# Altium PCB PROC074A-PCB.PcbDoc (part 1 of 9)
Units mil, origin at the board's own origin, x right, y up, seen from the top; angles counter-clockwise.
Board outline 2755.91 x 5300 mil, 10 copper layers (Top Layer, L2-GND, L3-SIG1, L4-GND, L5-PWR/SIG, L6-SIG2, L7-PWR2, L8-SIG3, L9-GND, Bottom Layer), stack 67.57 mil thick; 585 components, 490 nets, 2137 pads, 1150 vias.
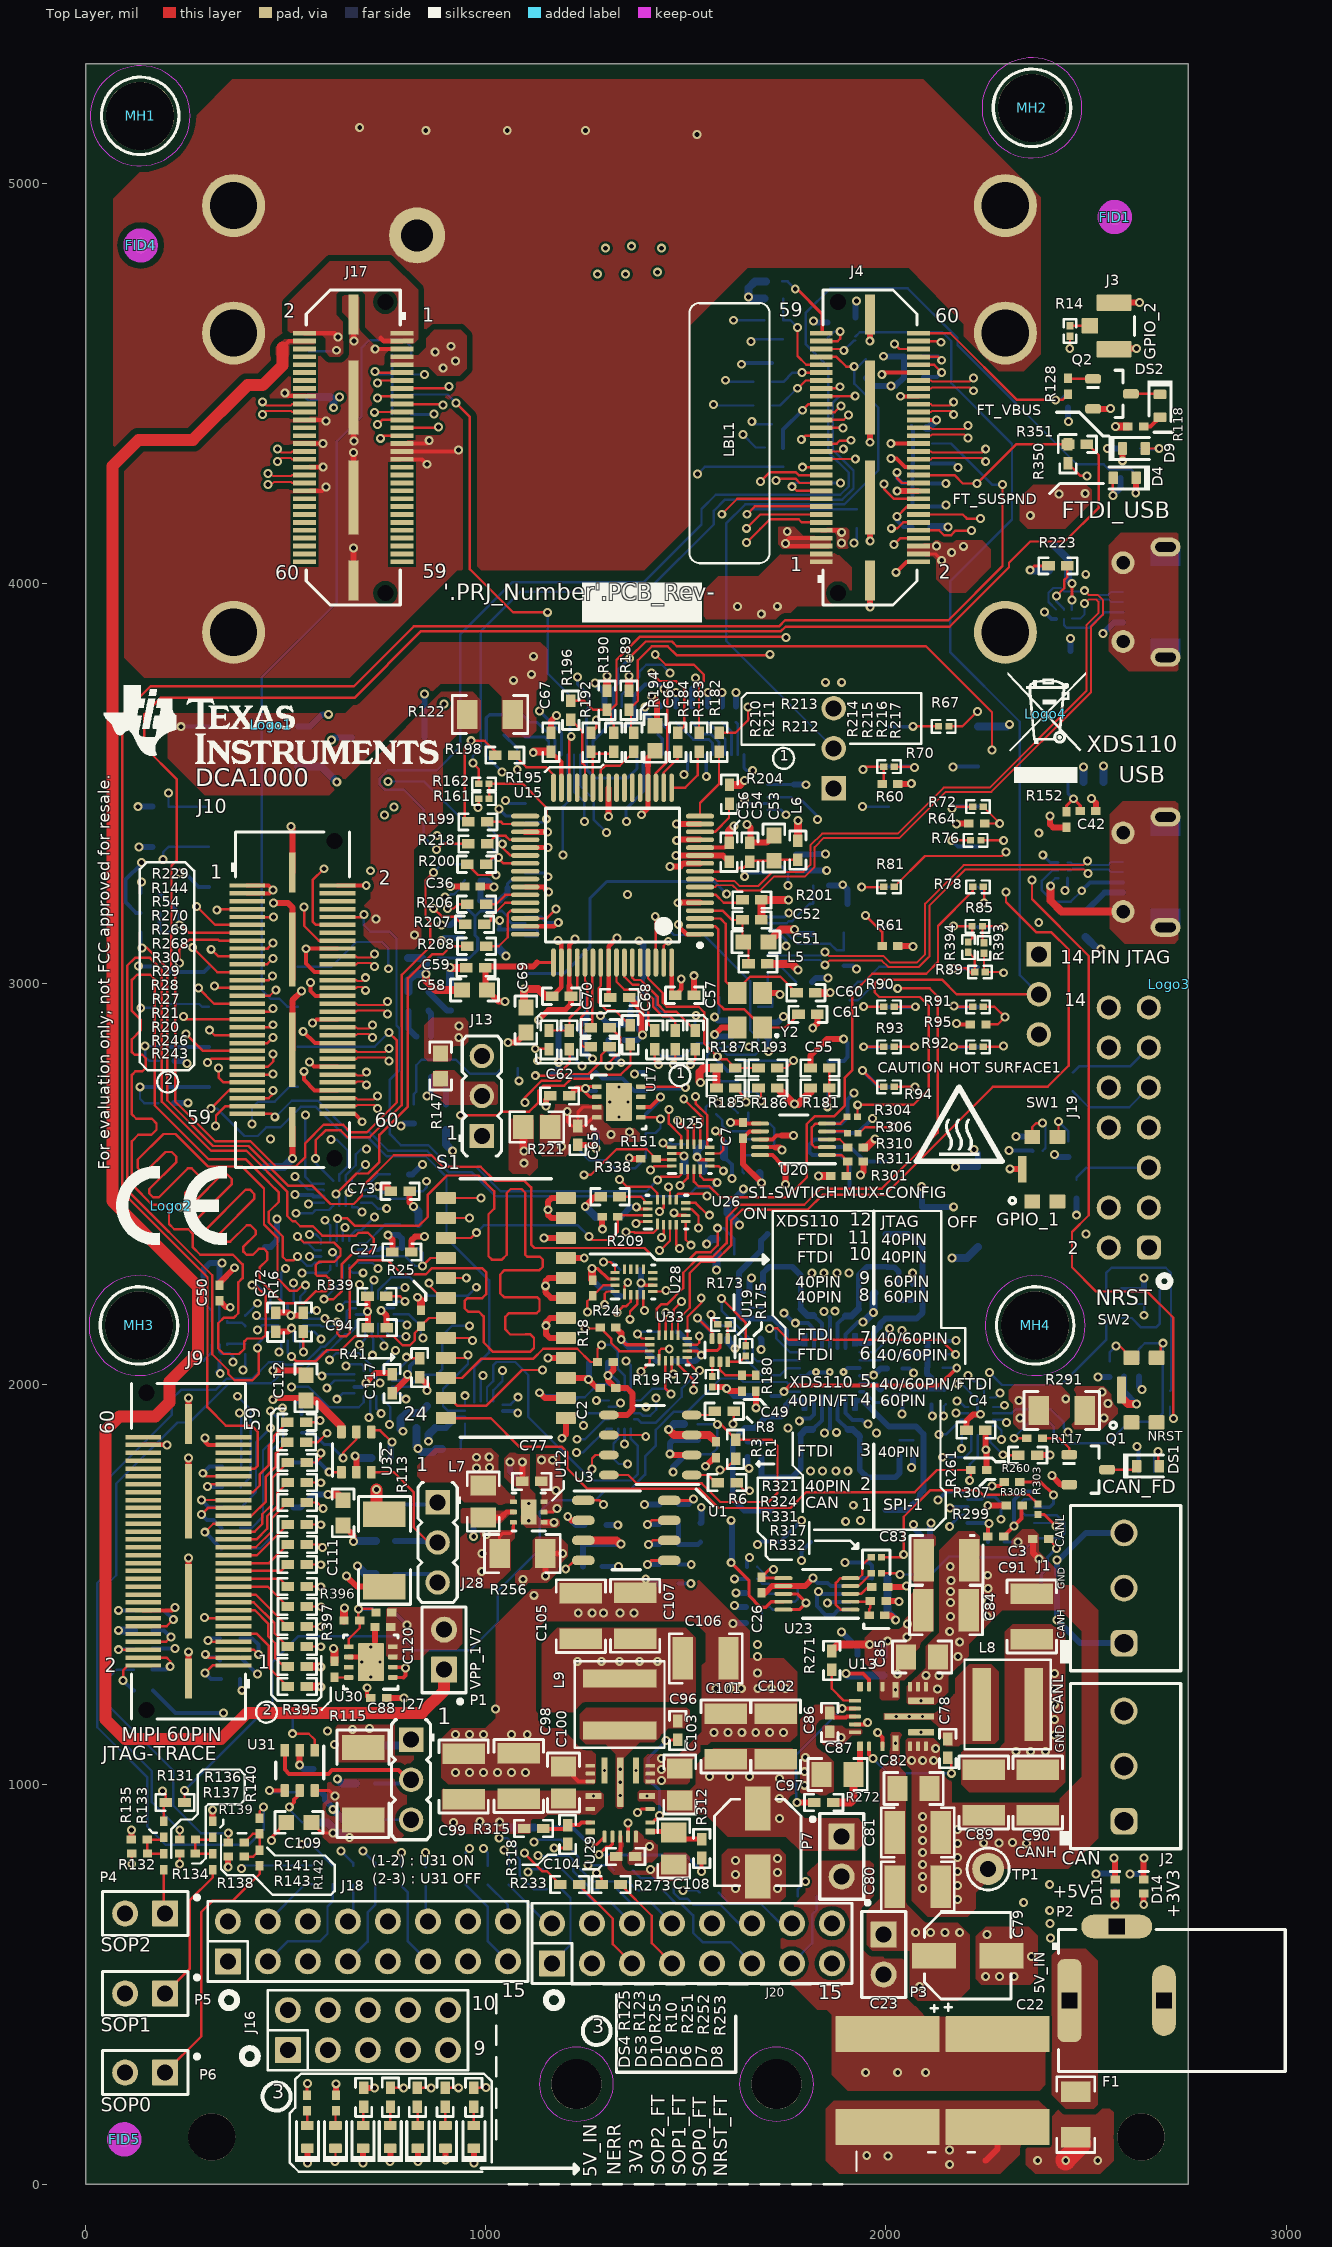
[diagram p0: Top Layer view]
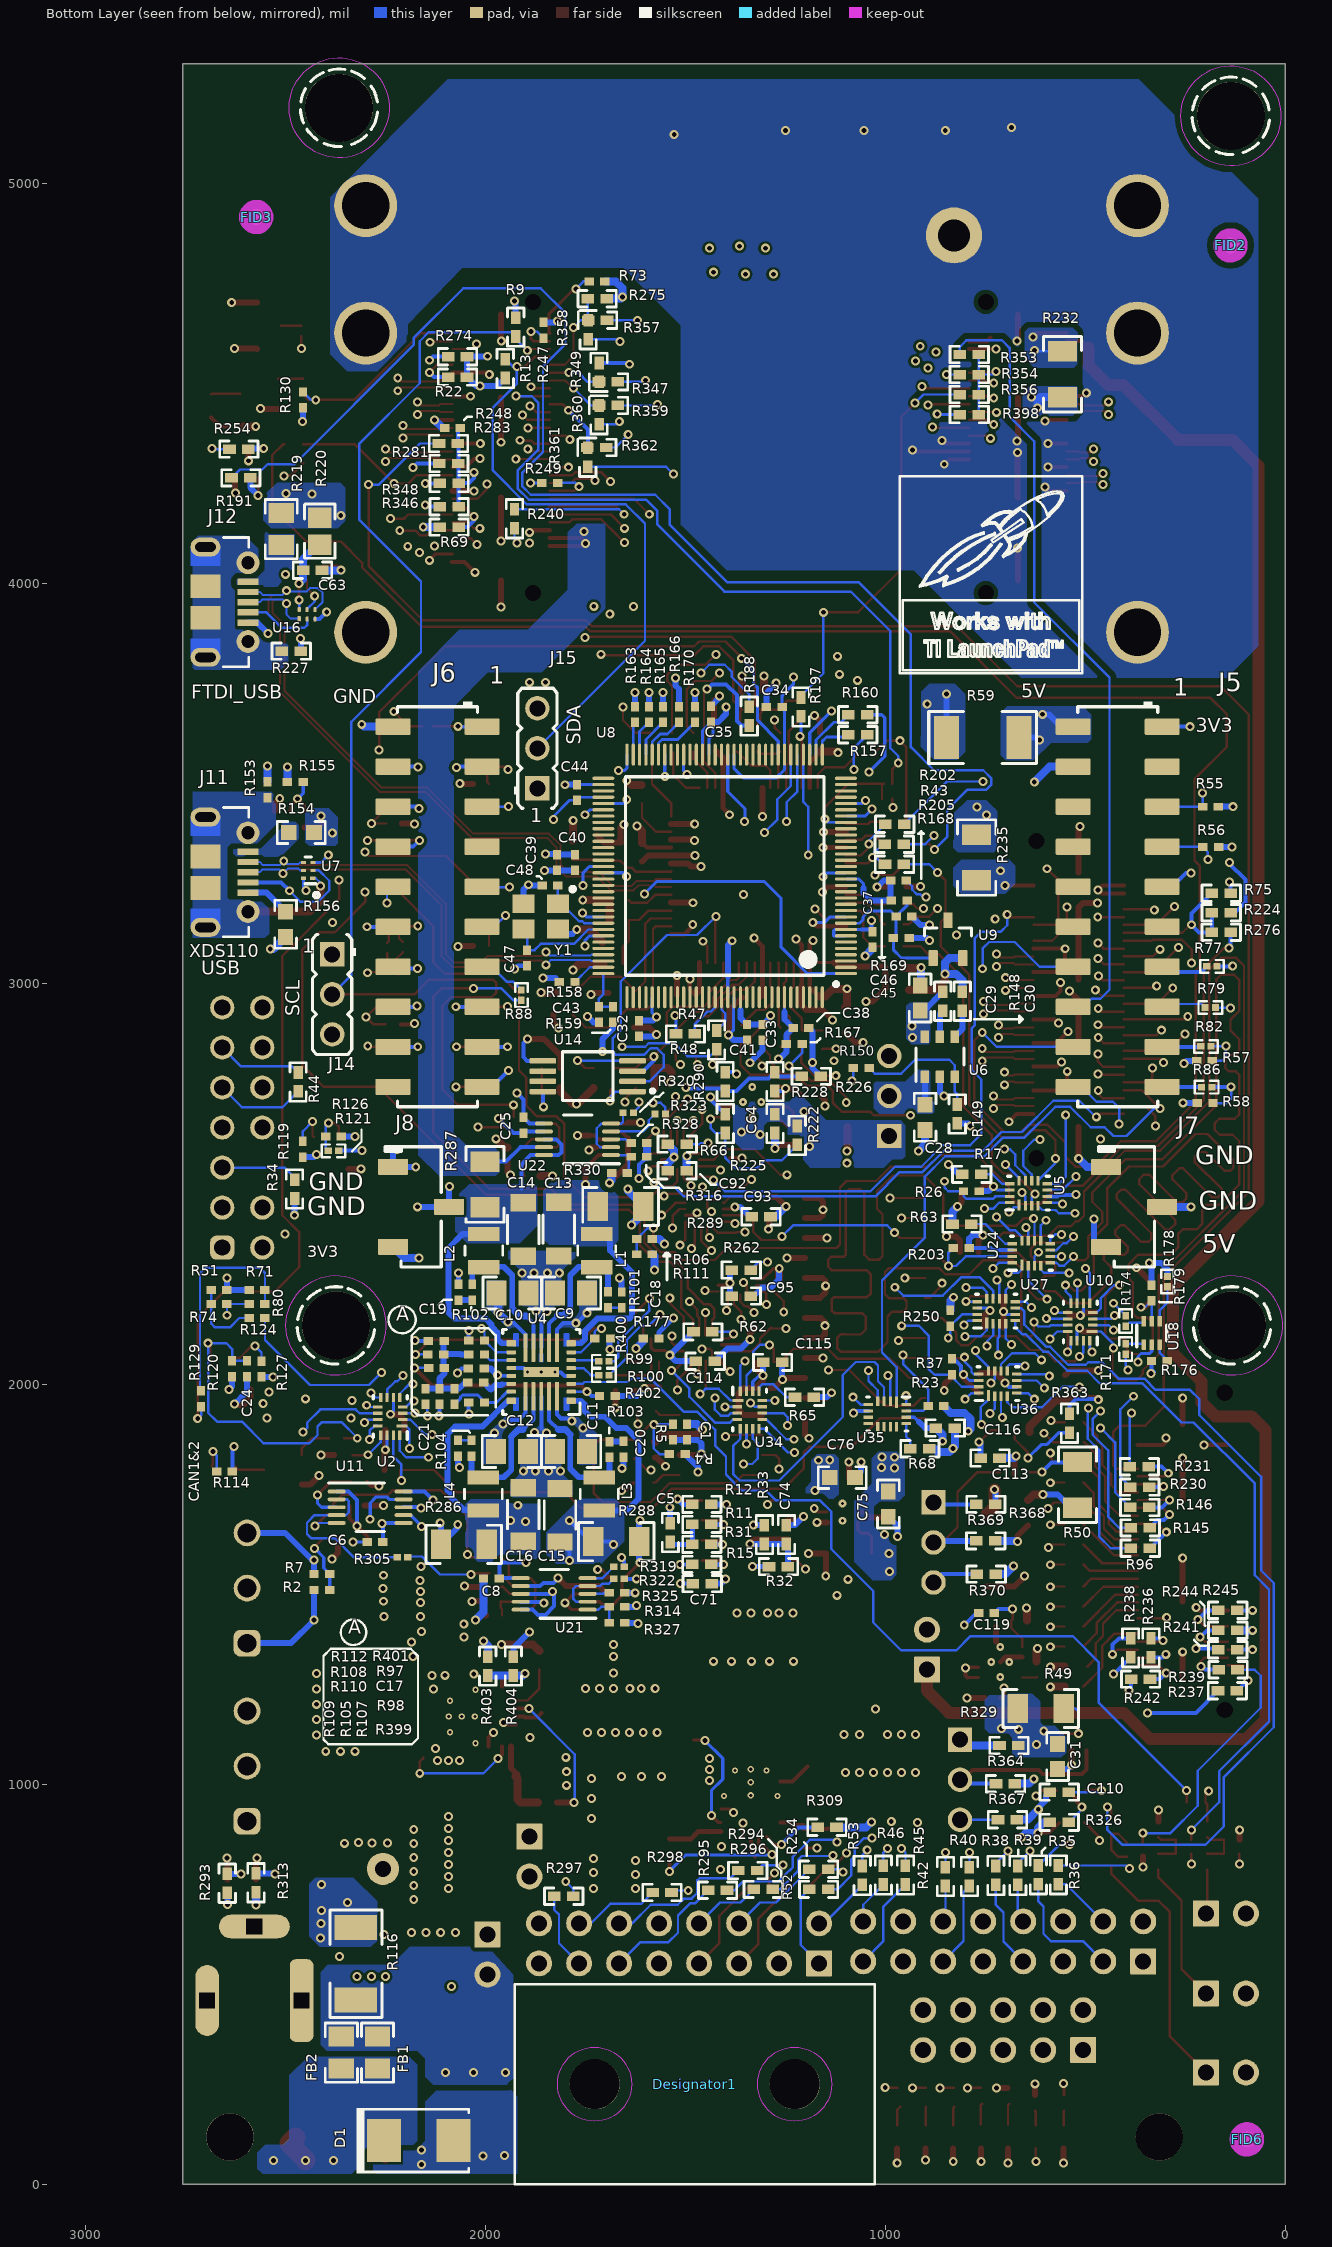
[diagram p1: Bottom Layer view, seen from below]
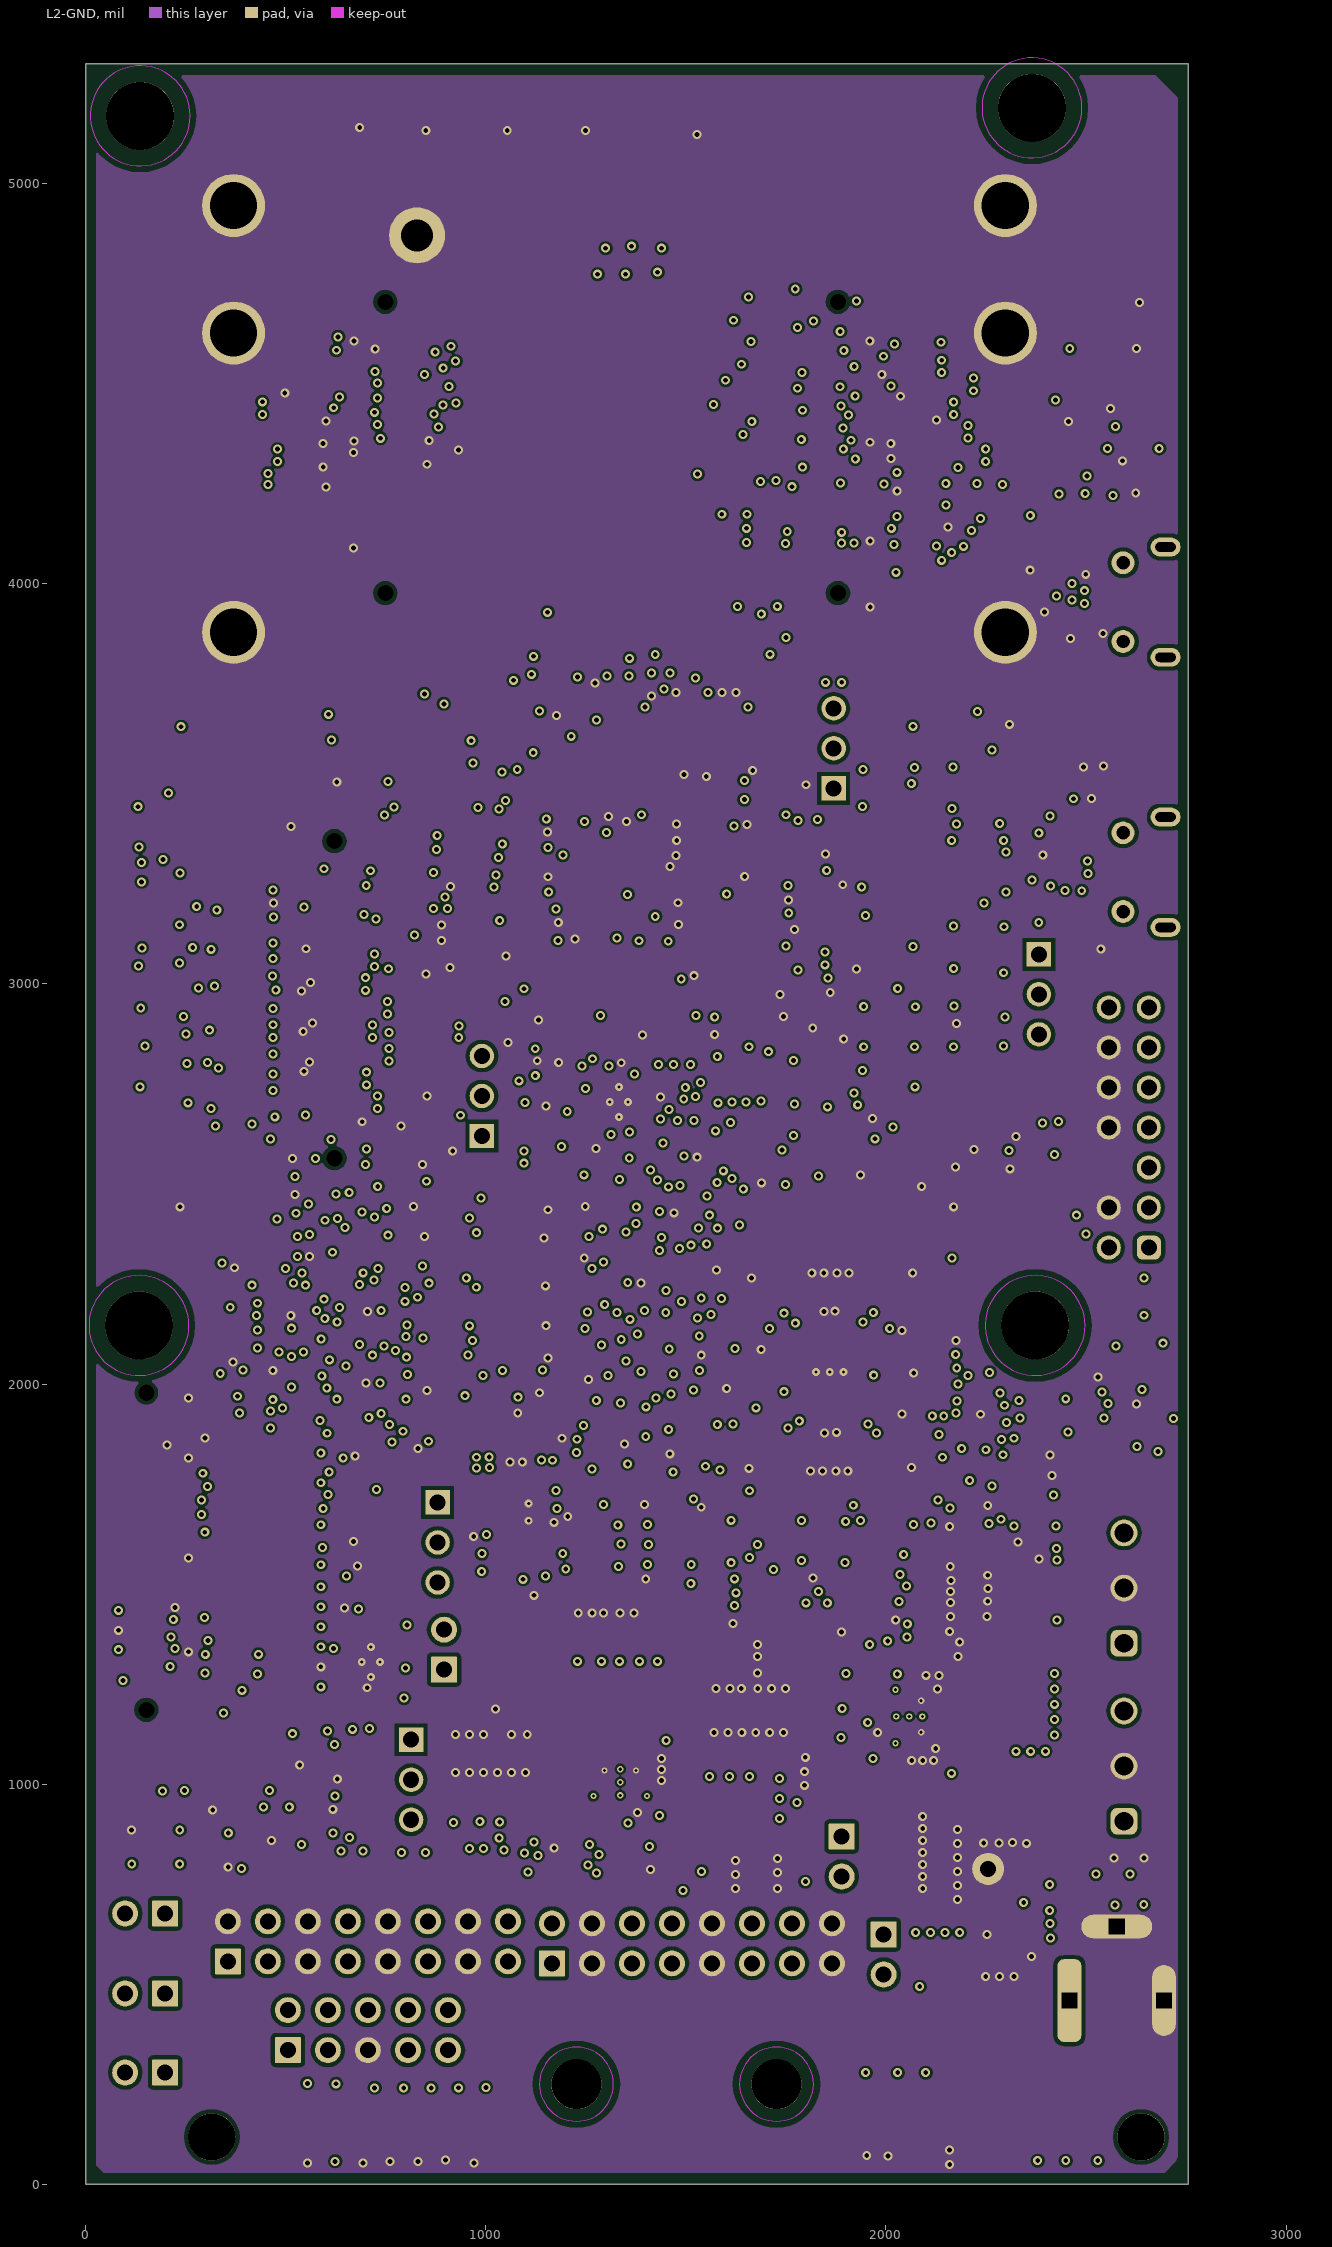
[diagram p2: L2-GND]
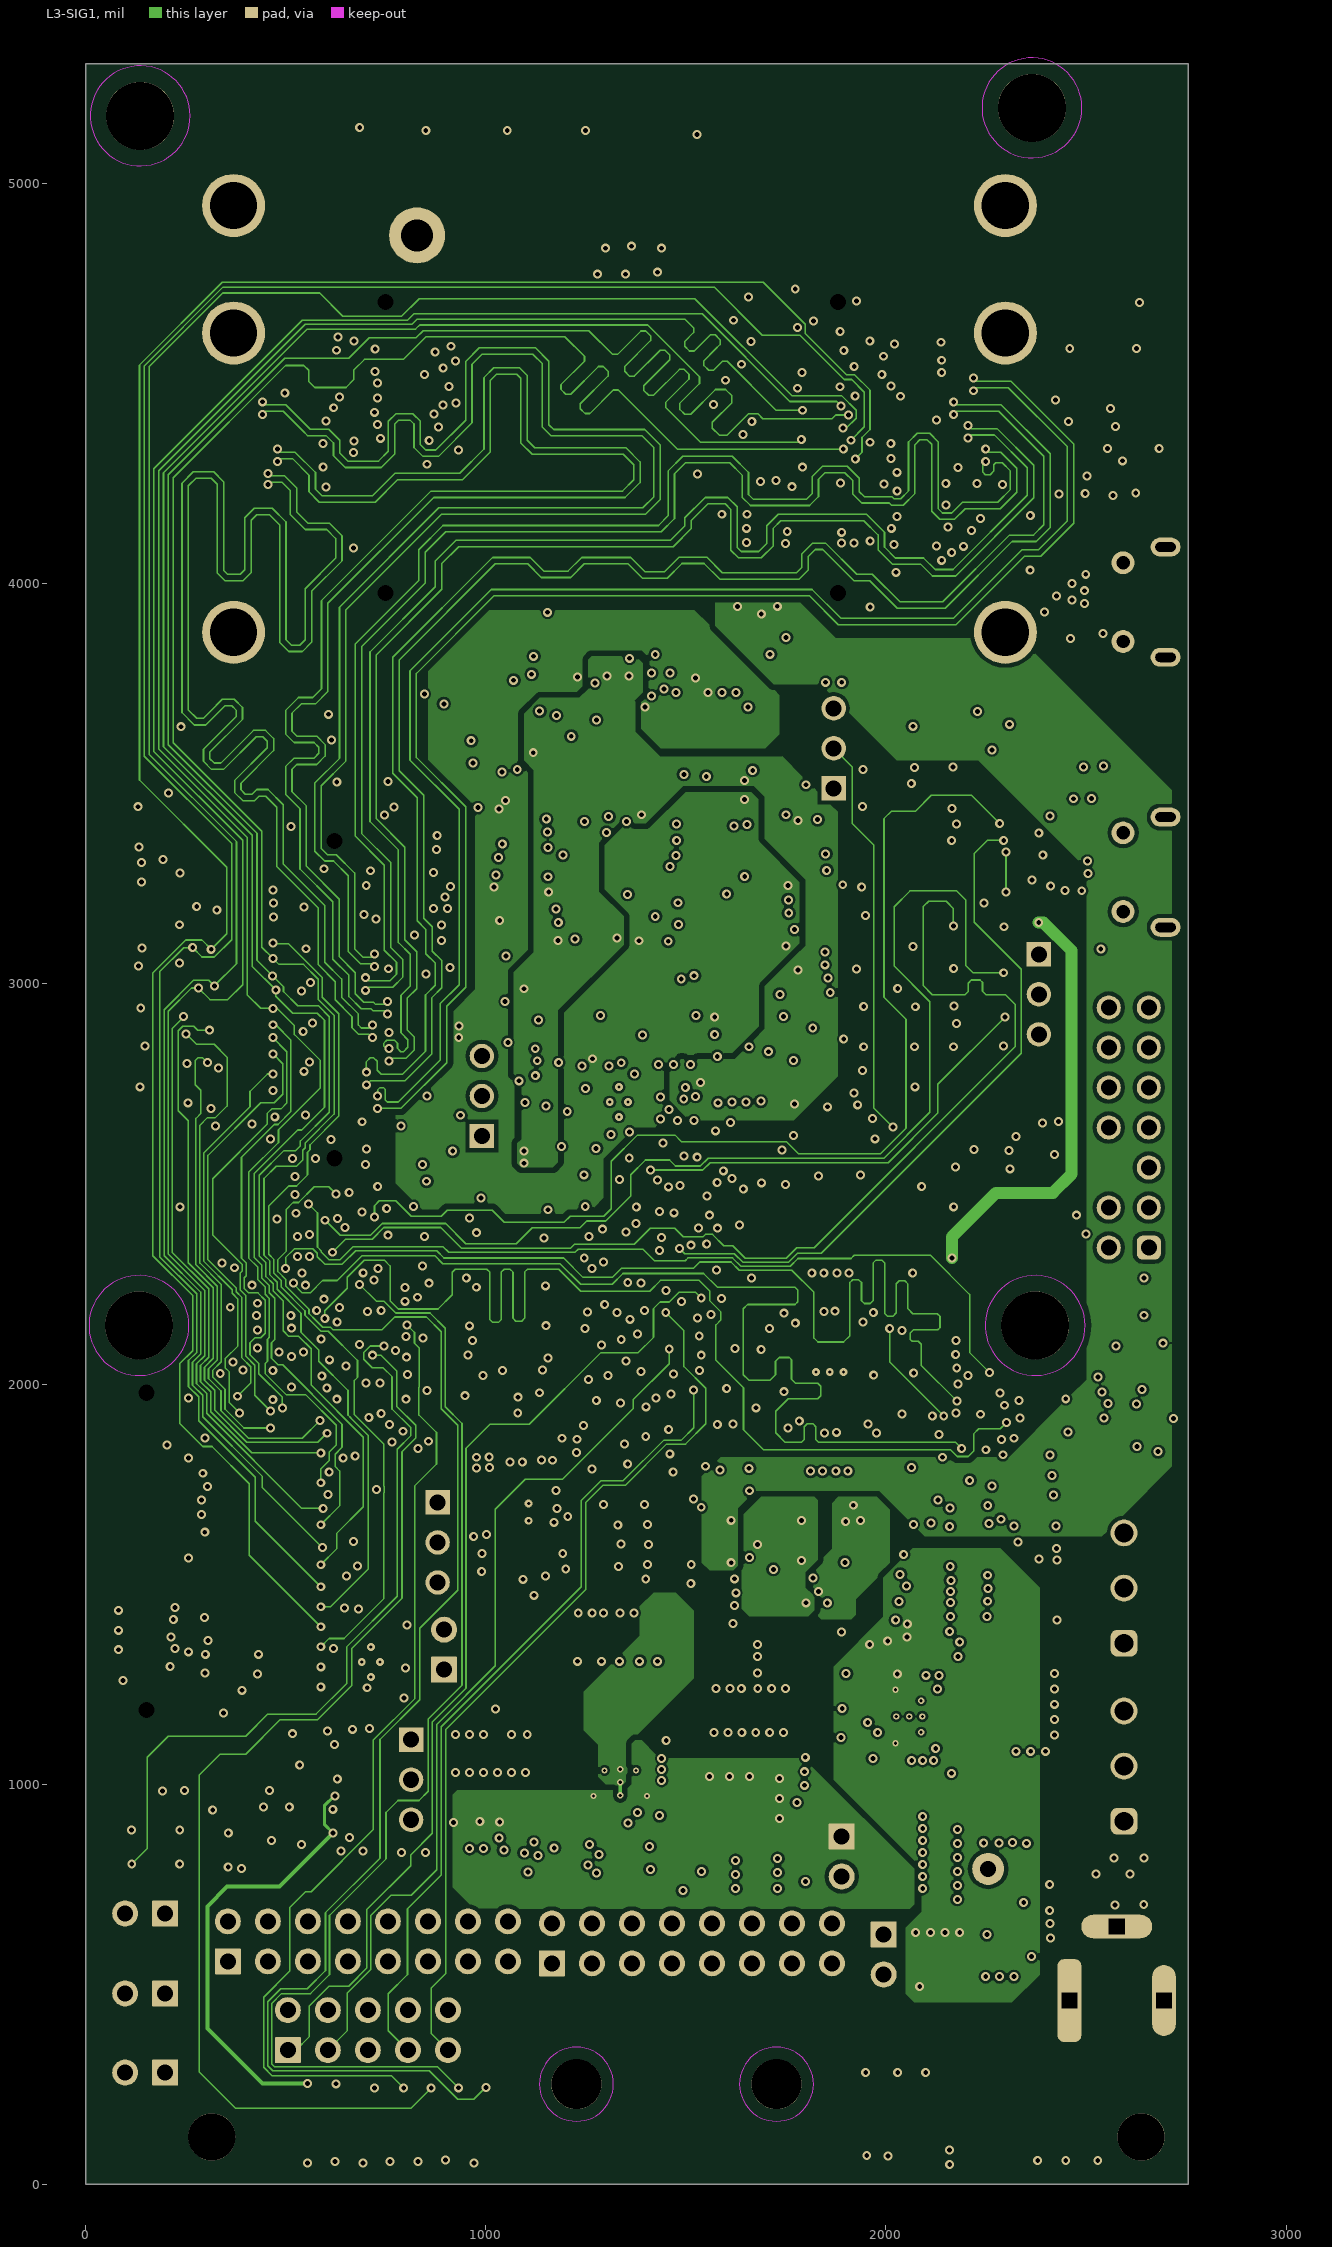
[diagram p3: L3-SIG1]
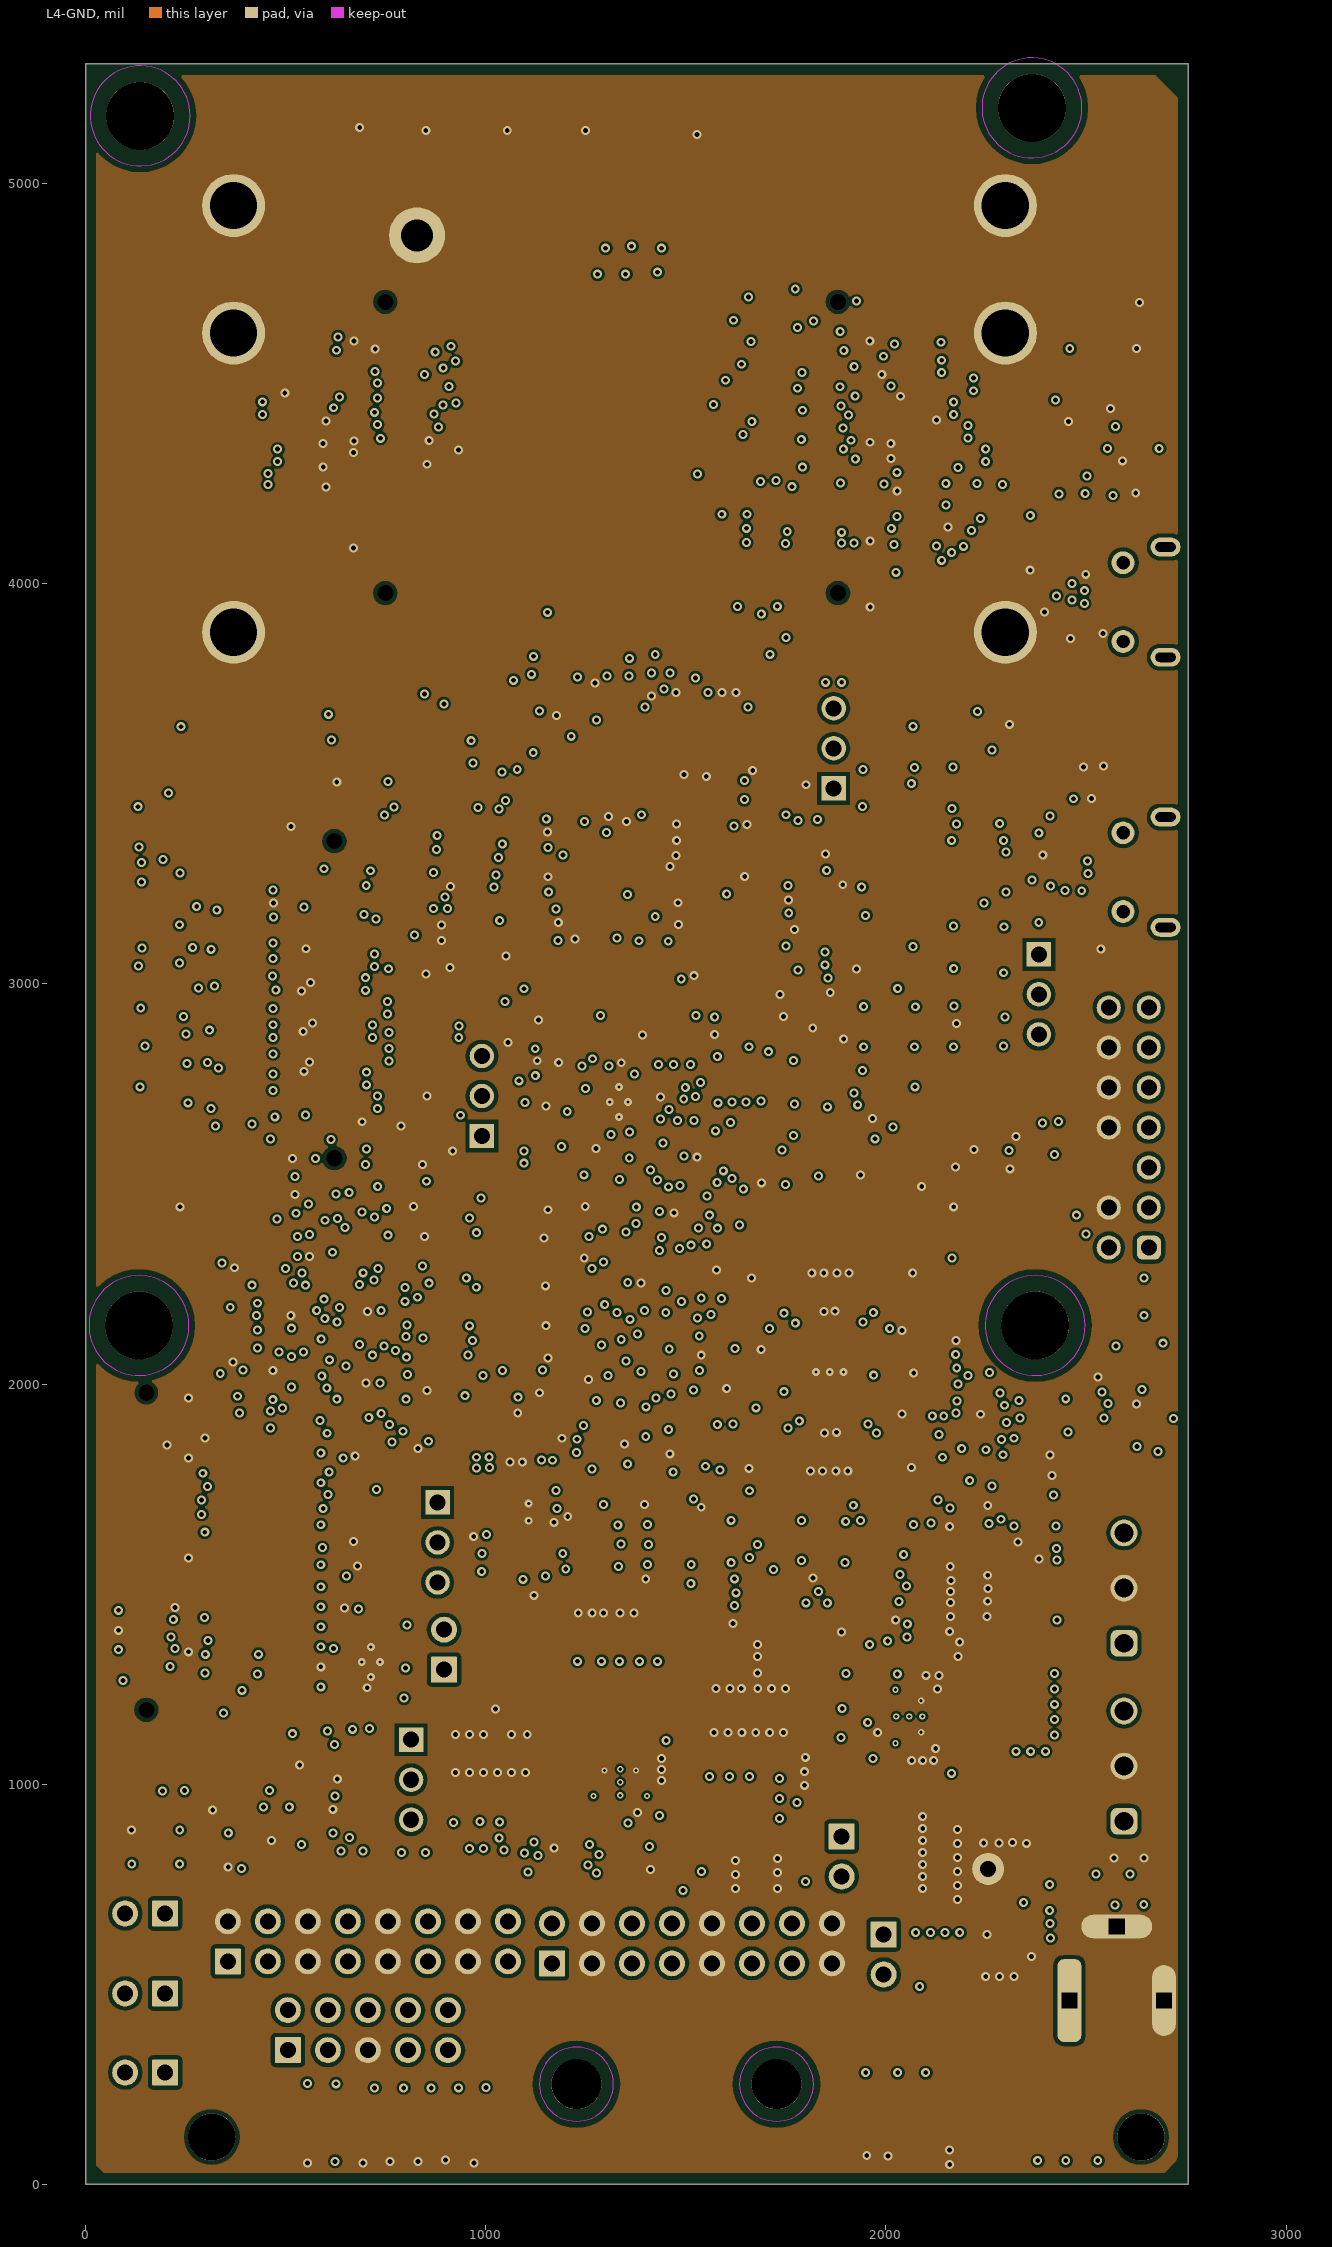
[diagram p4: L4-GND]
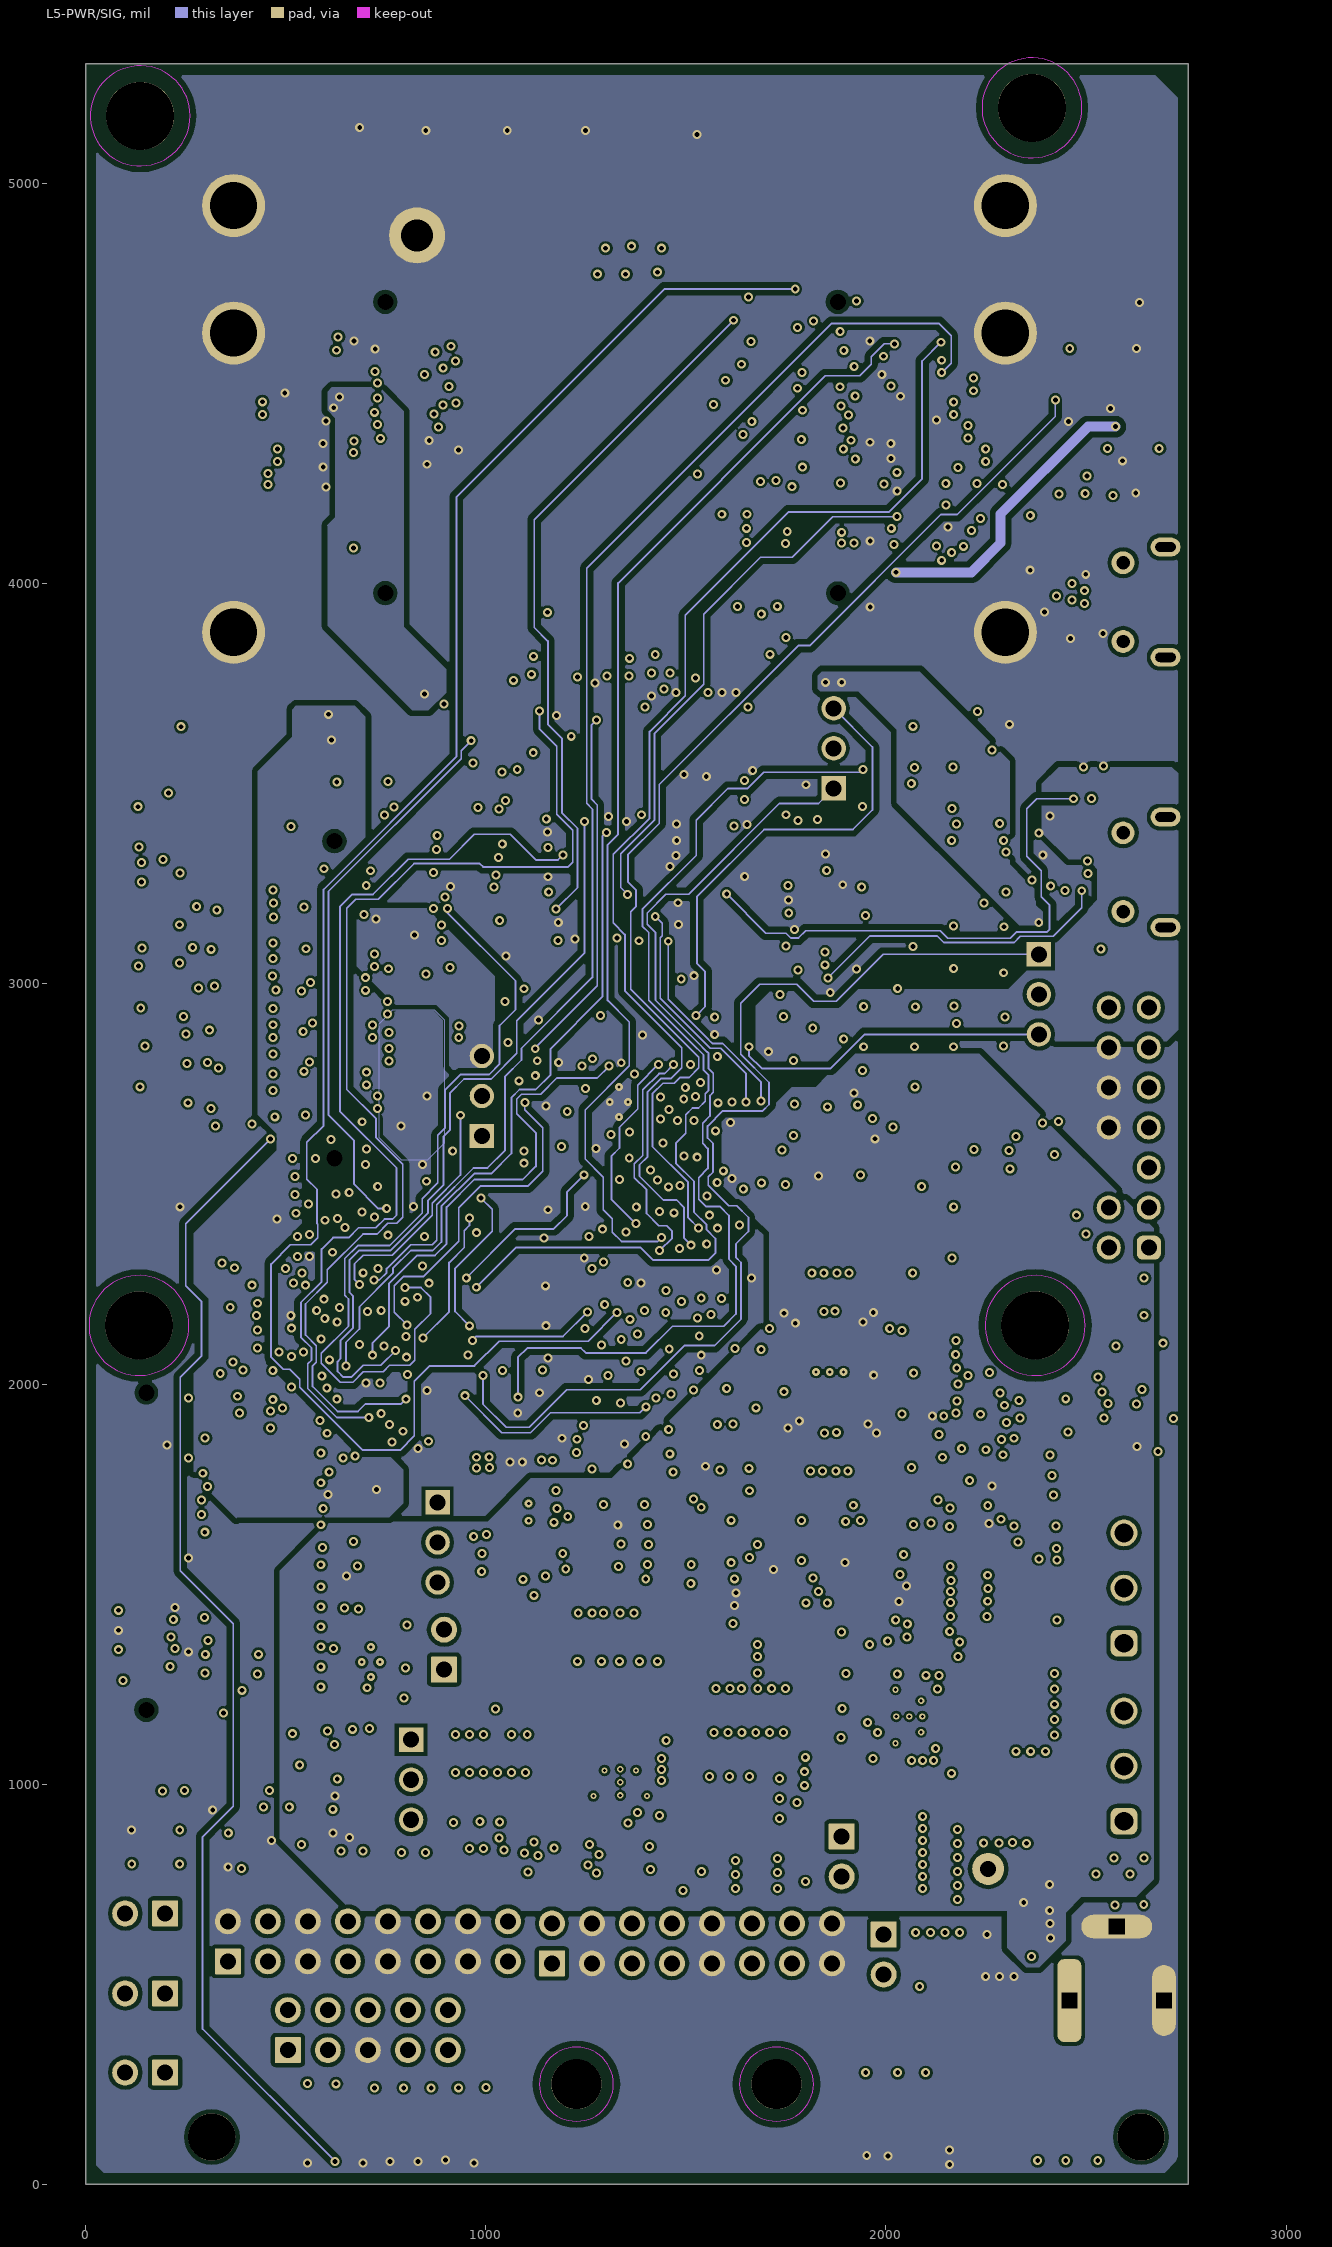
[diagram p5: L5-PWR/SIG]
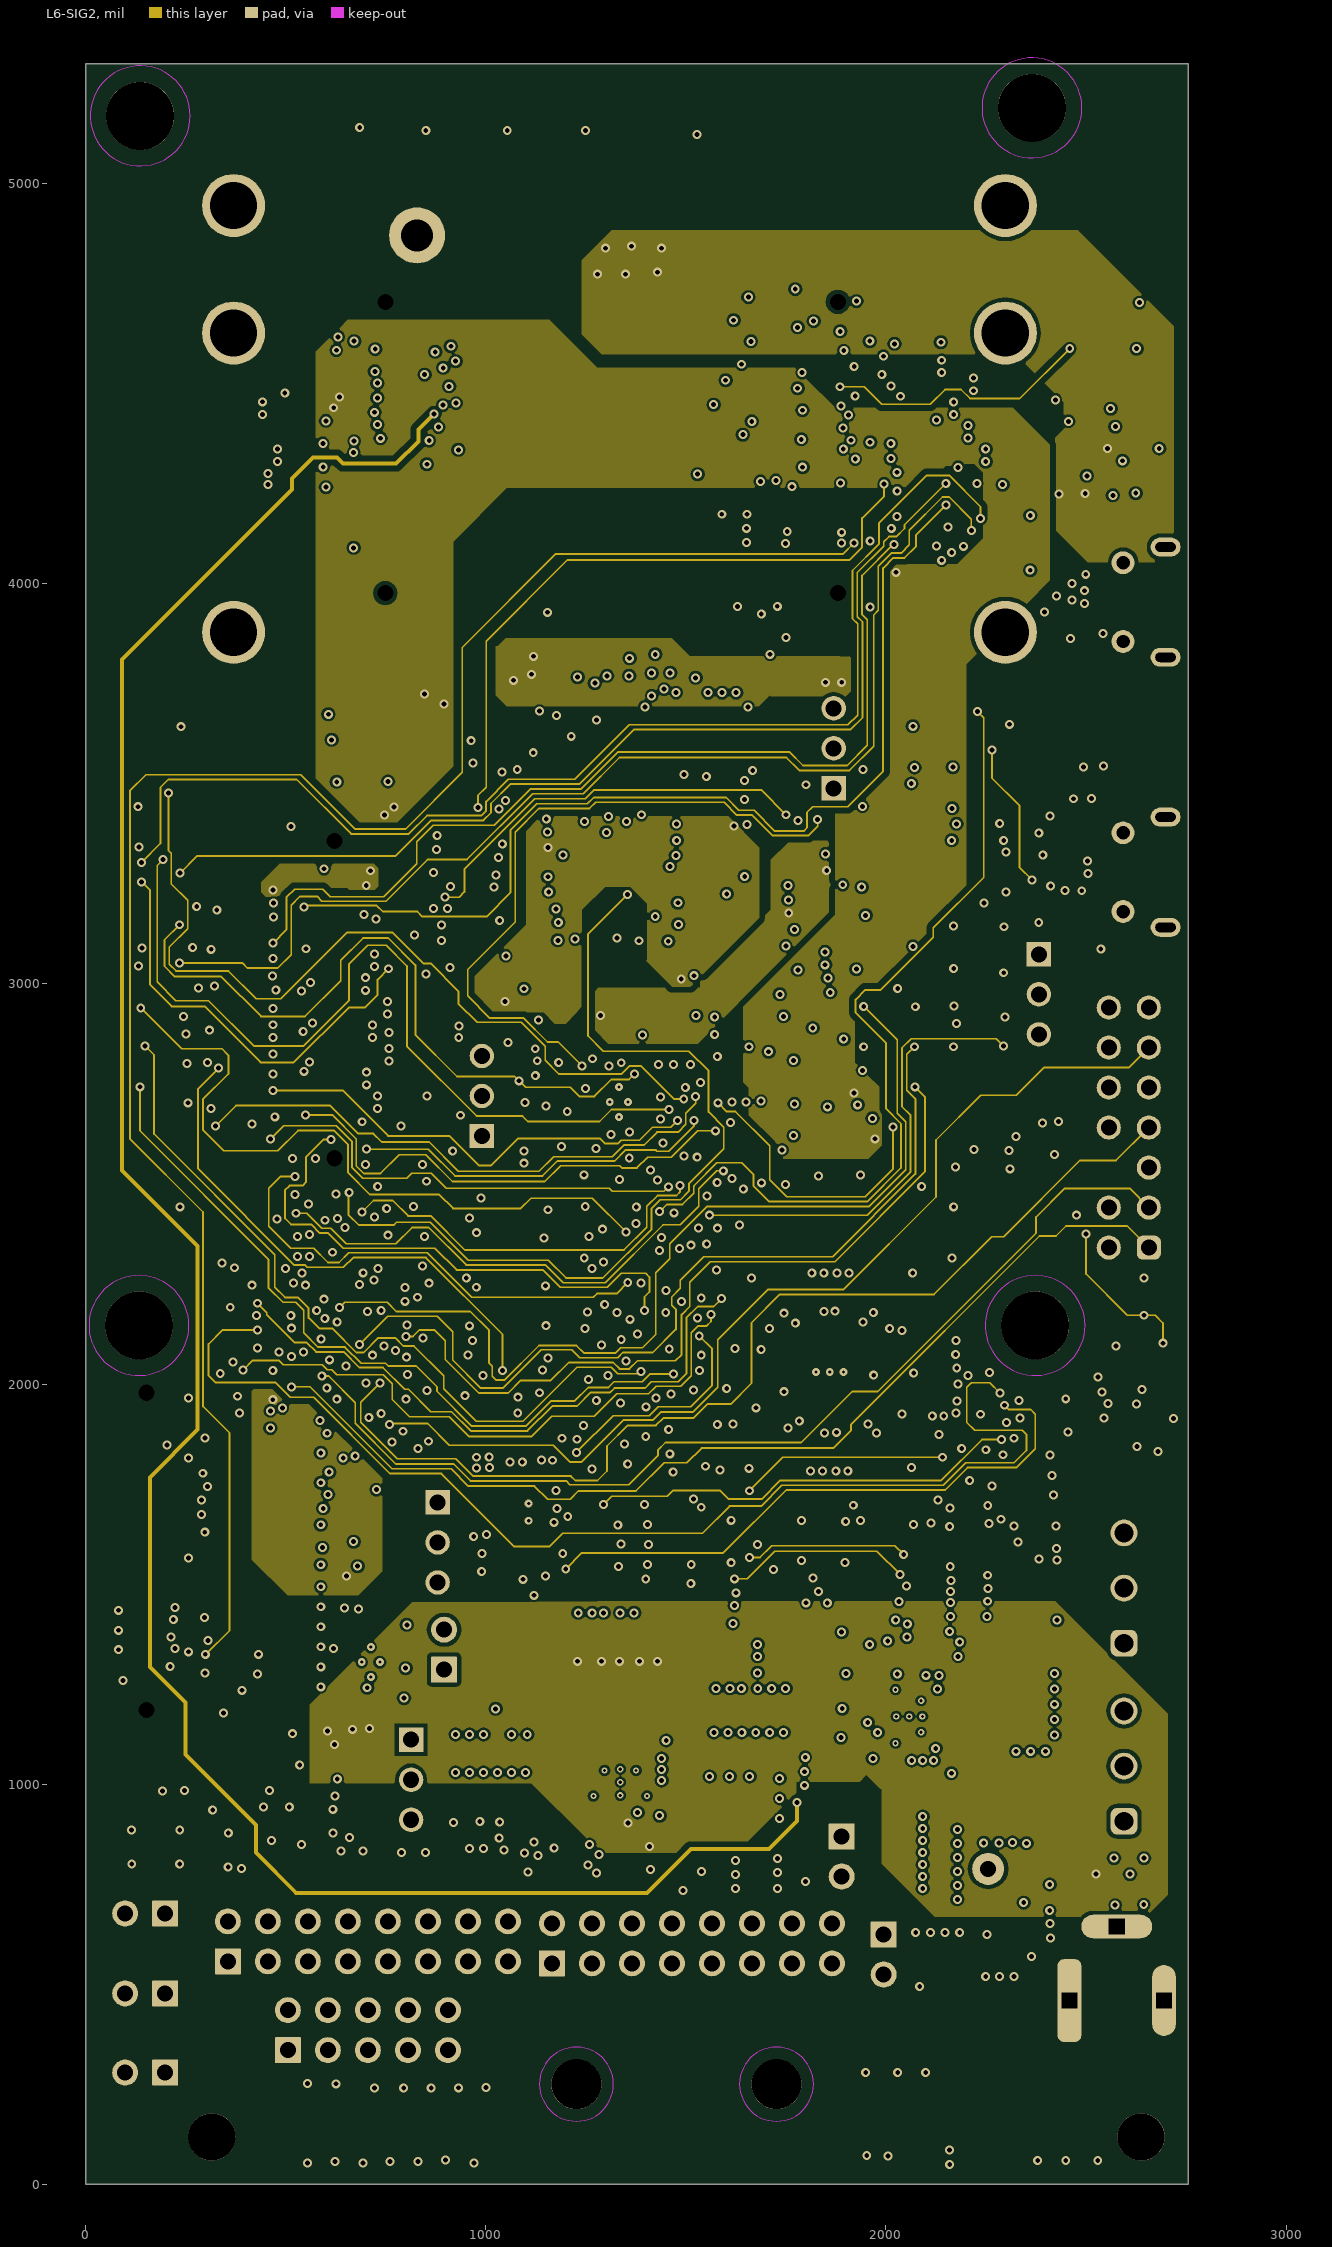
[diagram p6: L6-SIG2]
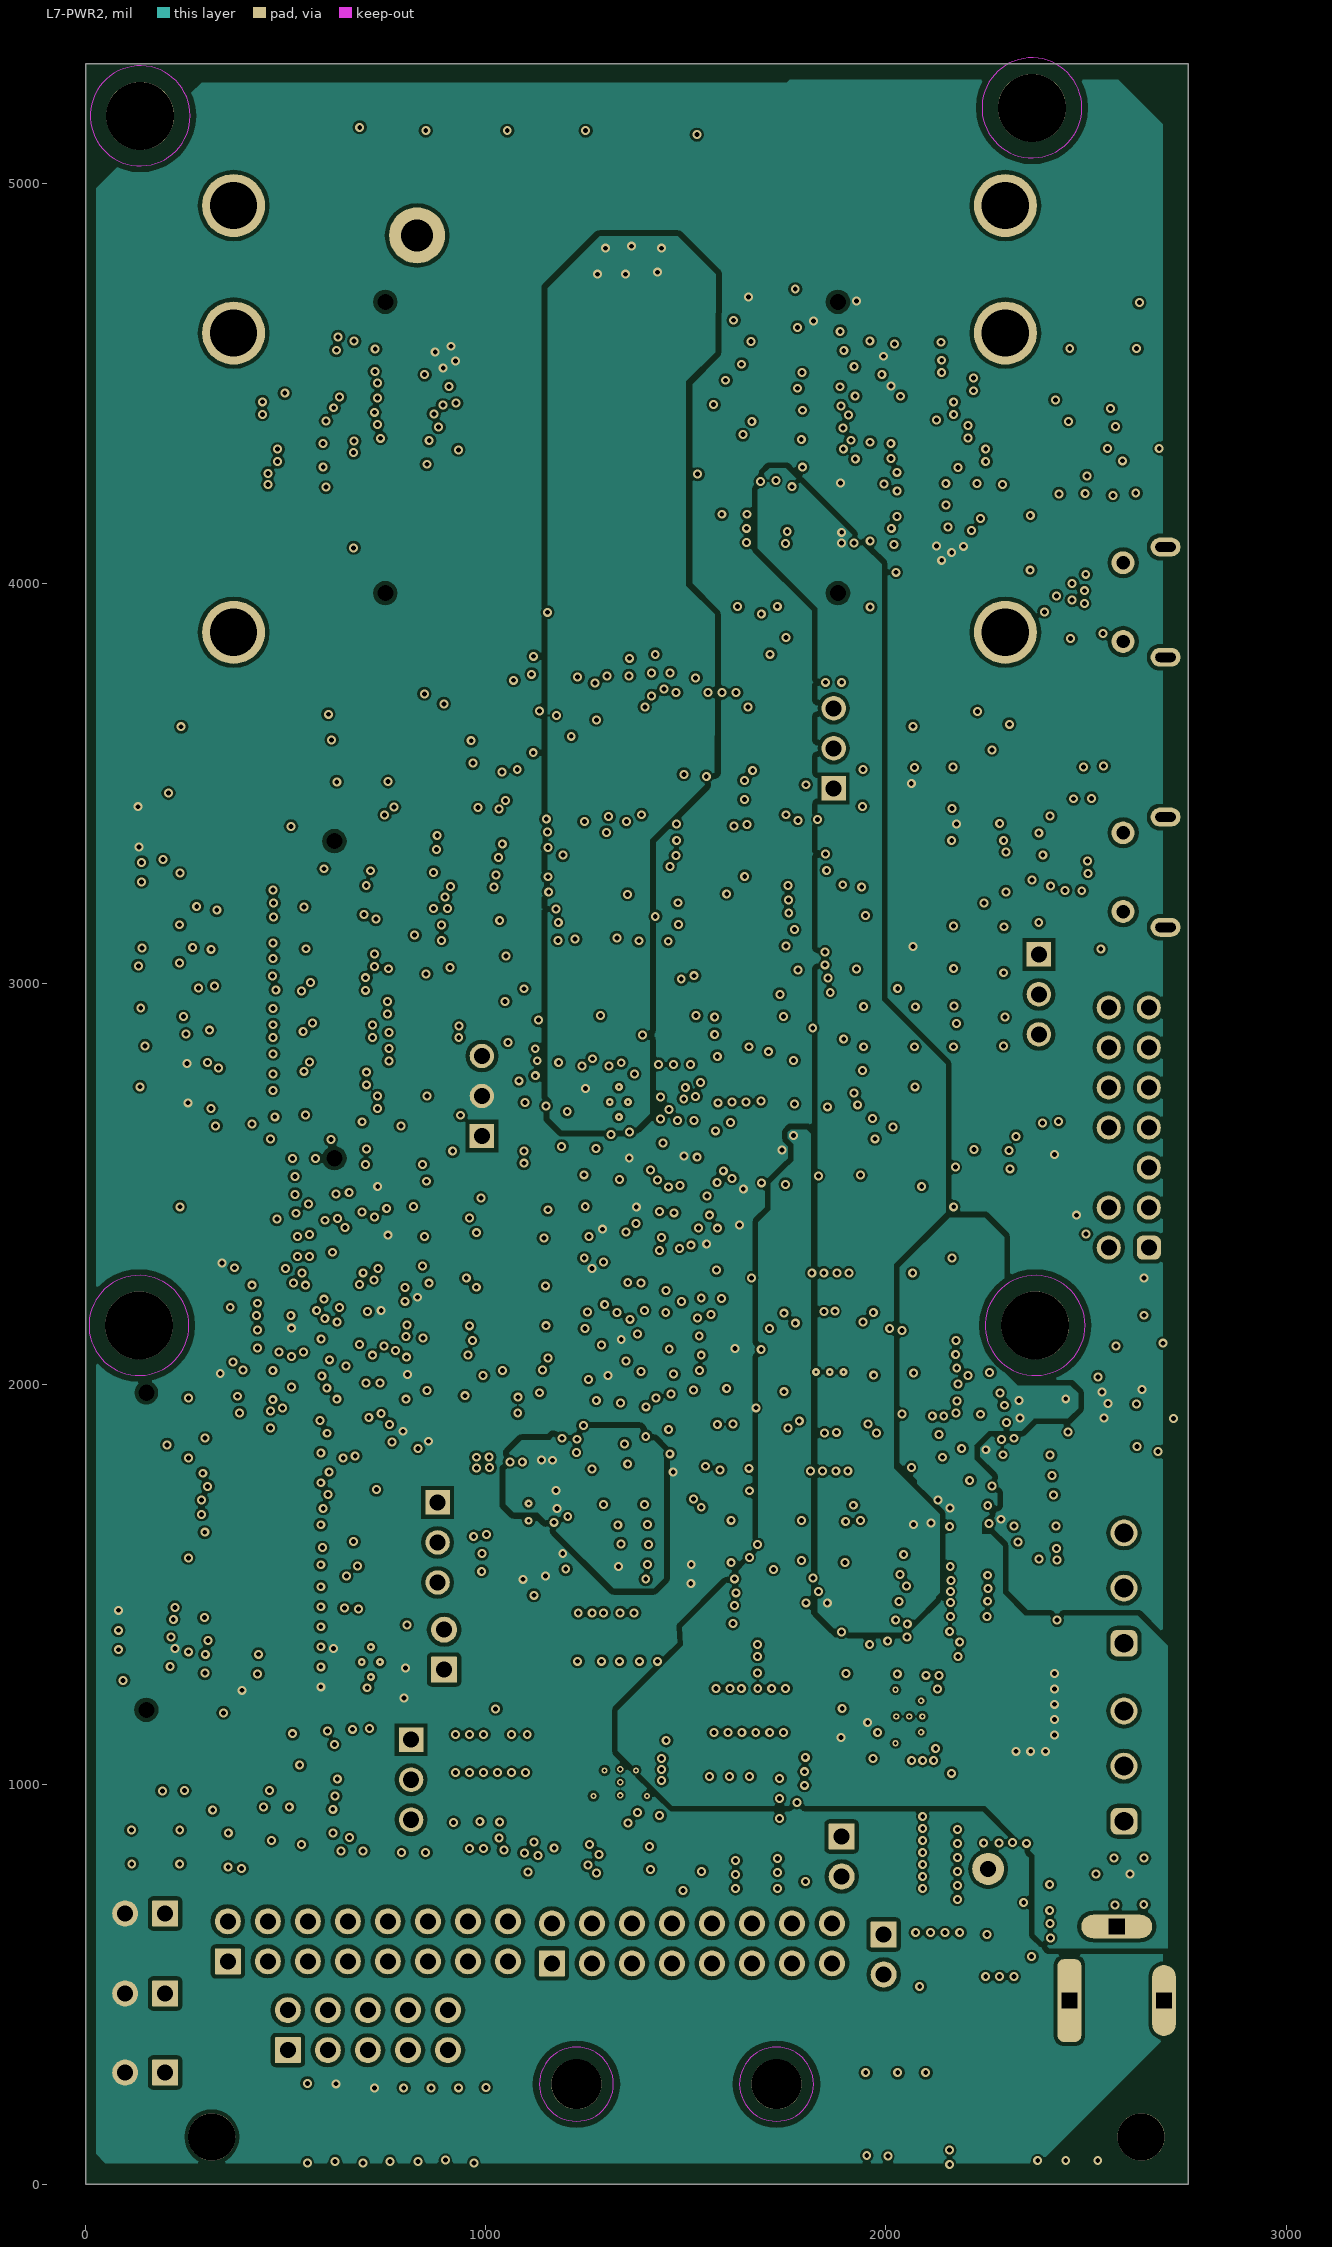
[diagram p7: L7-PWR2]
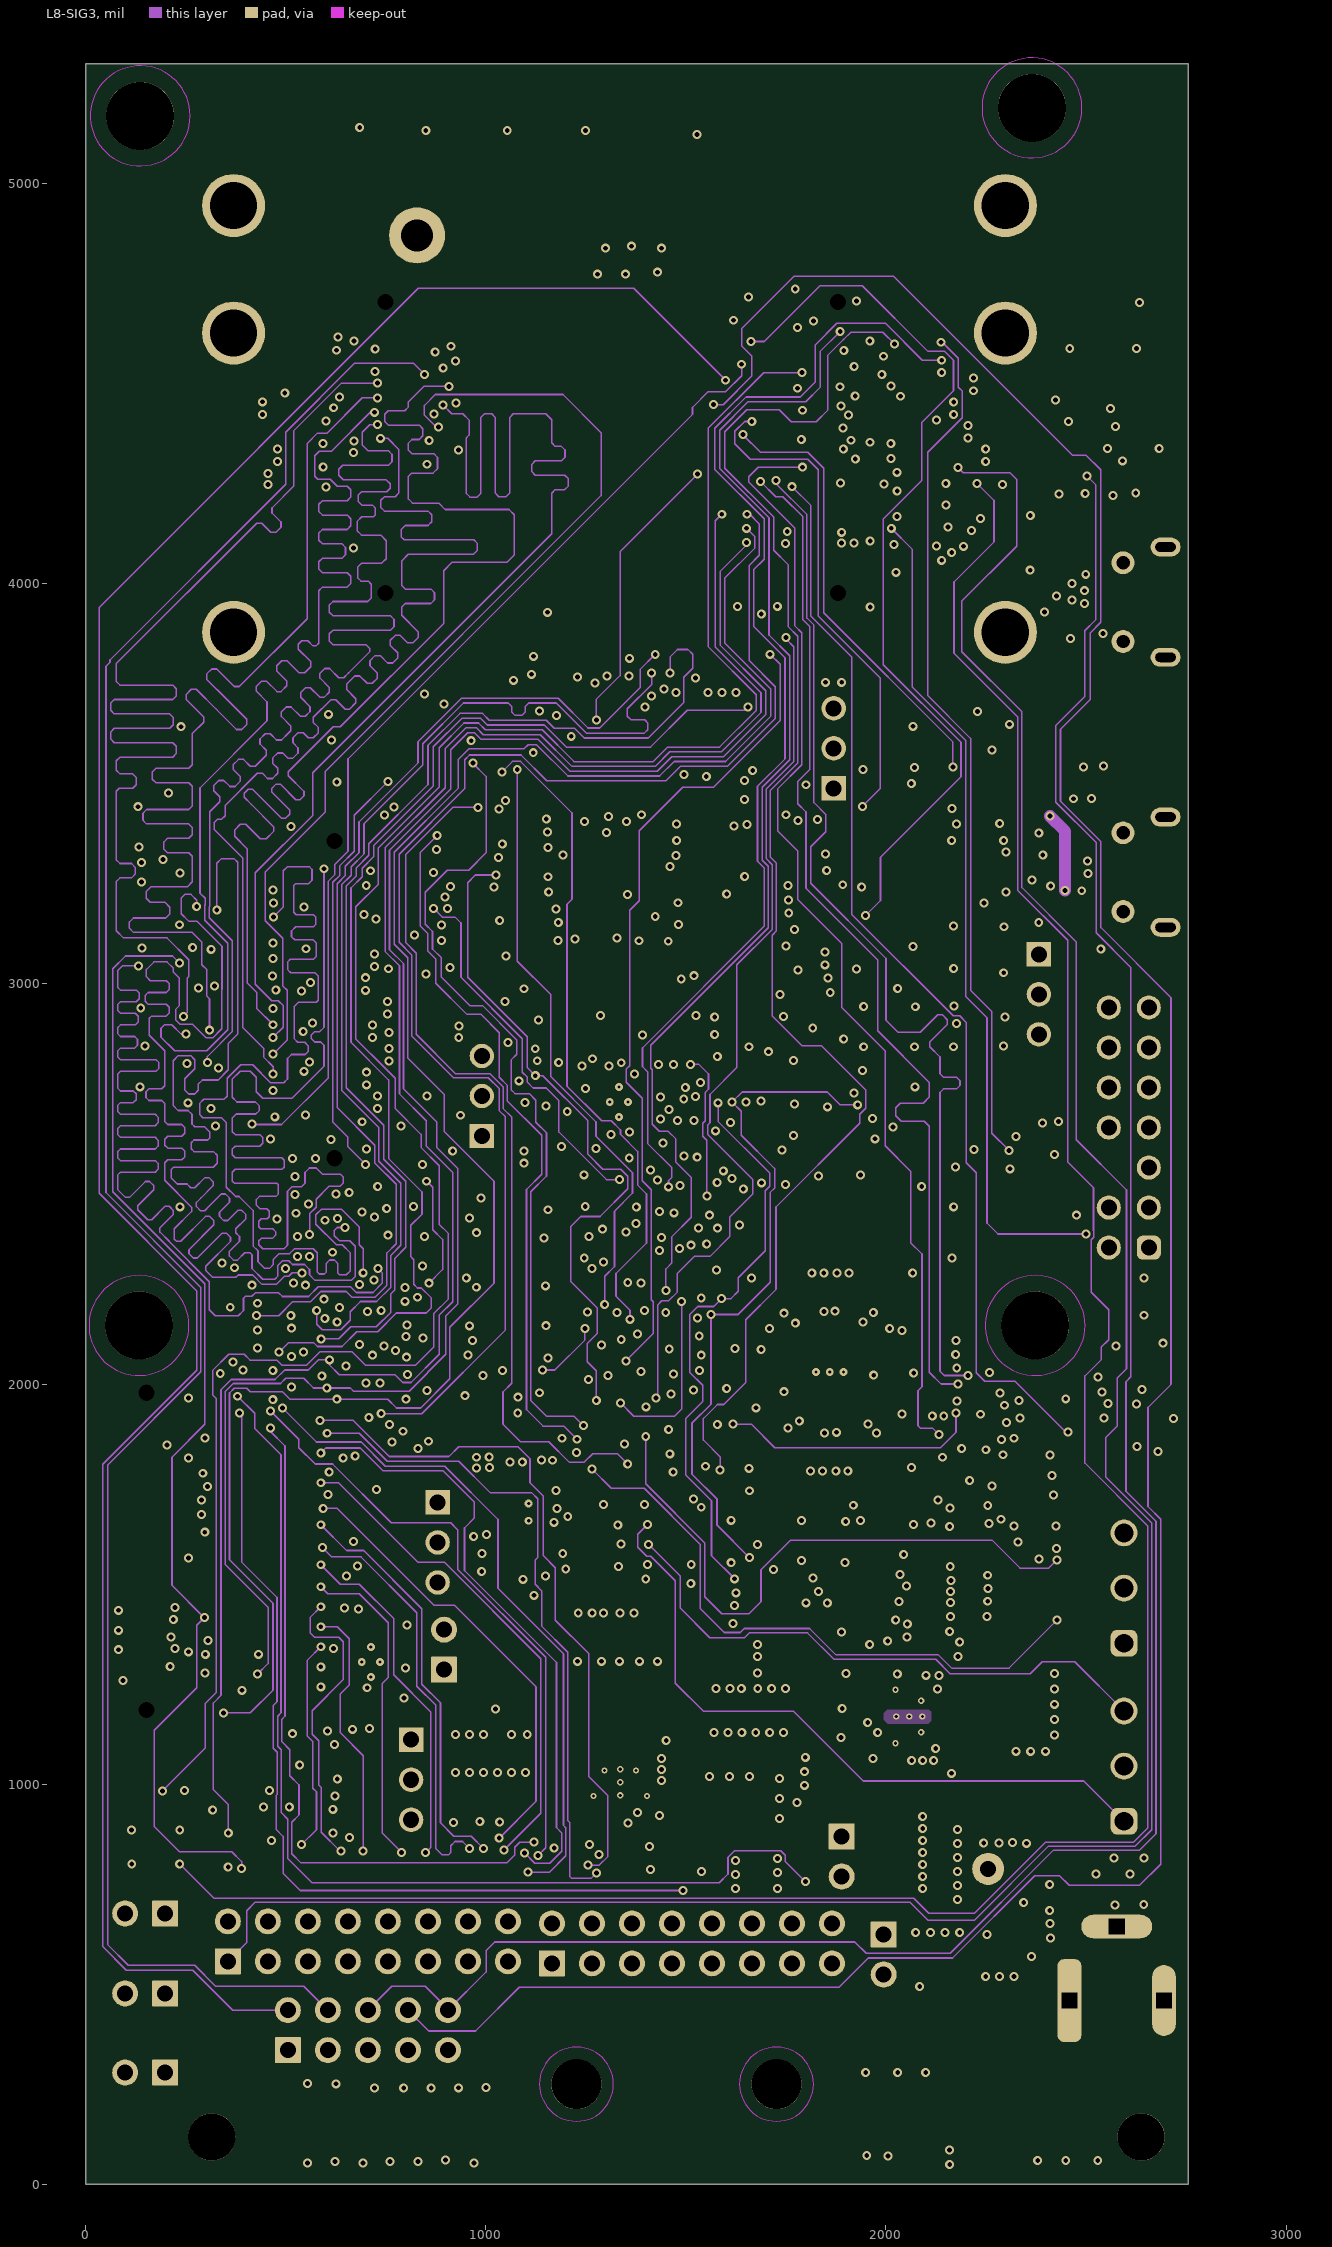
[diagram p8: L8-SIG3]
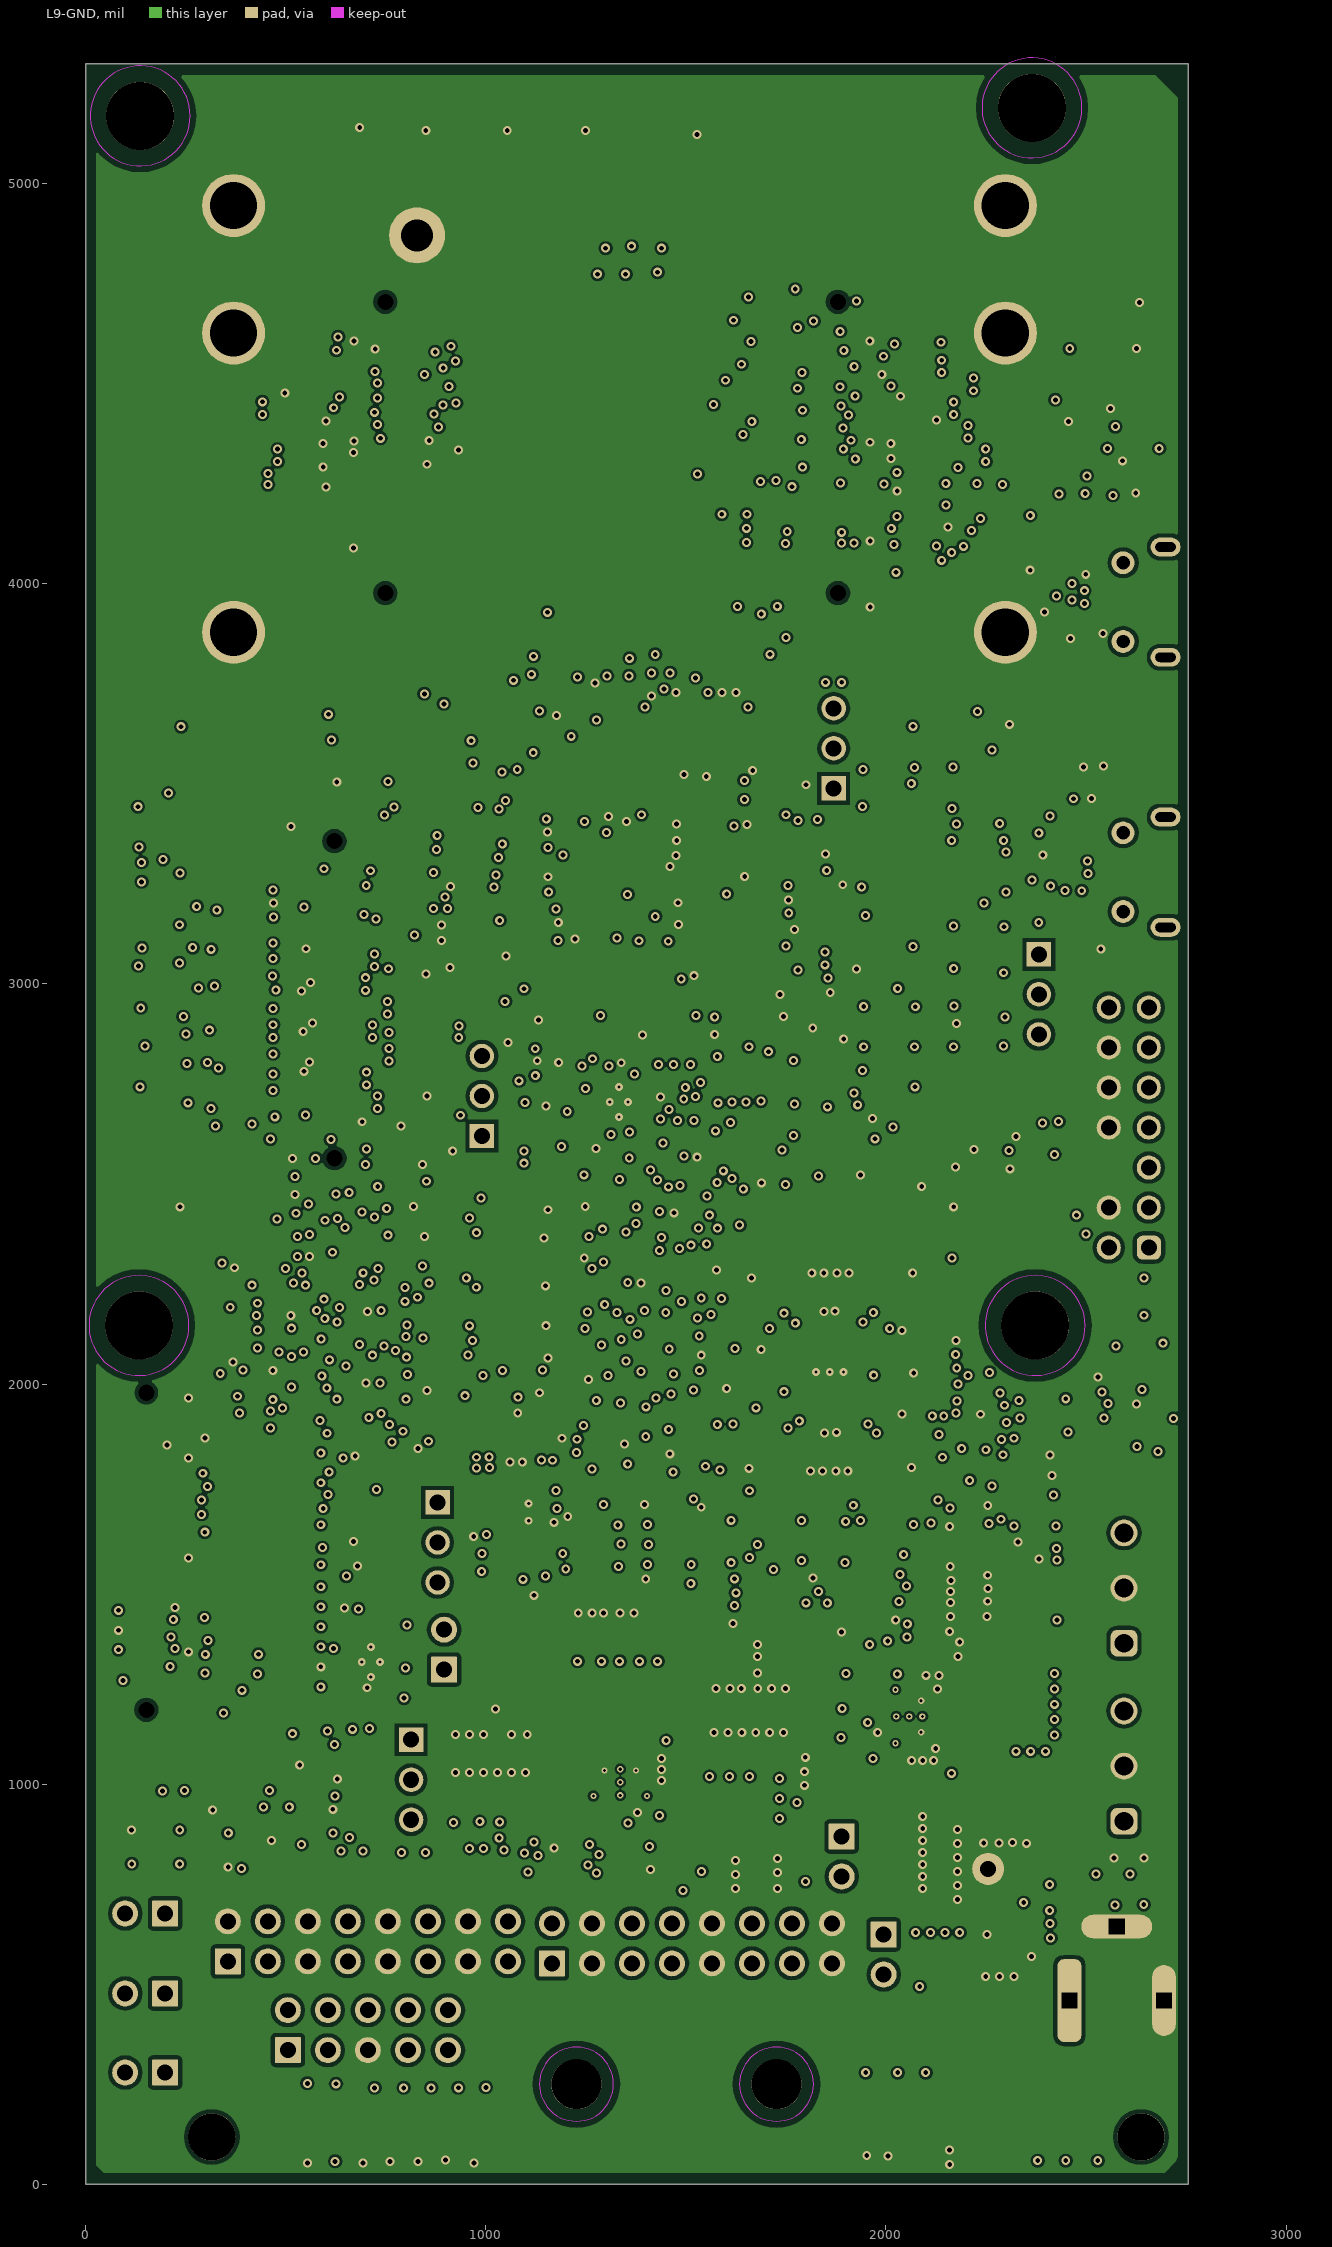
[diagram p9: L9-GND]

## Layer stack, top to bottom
Top Solder: solder mask 0.8, Solder Resist, Dk 1
Top Layer: signal copper 1.8
Dielectric1: prepreg 3.87, FR-4, Dk 4.02
L2-GND: signal copper 1.2
Dielectric 2: core 4, FR-4, Dk 4.26
L3-SIG1: signal copper 1.2
Dielectric 3: prepreg 8.7, FR-4, Dk 4.06
L4-GND: signal copper 1.2
Dielectric 4: core 4, FR-4, Dk 4.26
L5-PWR/SIG: signal copper 1.2
Dielectric 5: prepreg 13.51, FR-4, Dk 4.06
L6-SIG2: signal copper 1.2
Dielectric 6: core 4, FR-4, Dk 4.26
L7-PWR2: signal copper 1.2
Dielectric 7: prepreg 8.42, FR-4, Dk 4.06
L8-SIG3: signal copper 1.2
Dielectric 8: core 4, FR-4, Dk 4.26
L9-GND: signal copper 1.2
Dielectric 9: prepreg 3.87, FR-4, Dk 4.02
Bottom Layer: signal copper 1.8
Bottom Solder: solder mask 0.8, Solder Resist, Dk 1

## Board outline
0,0 0,5300 2755.91,5300 2755.91,0

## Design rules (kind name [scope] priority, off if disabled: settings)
AcuteAngle [All] p1: minimum=4.50000000000000E+0001 checktracksonly=FALSE
AssemblyTestPointUsage [All] p1: valid=2
BoardOutlineClearance BoardOutlineClearance_MountingHoles [OnCopper and InComponentClass('Mounting Holes')] p1: gap=40 ignorepadtopadclearanceinfootprint=FALSE
BoardOutlineClearance BoardOutlineClearance_Poly [OnCopper and IsPoly] p2: gap=25 ignorepadtopadclearanceinfootprint=FALSE
BoardOutlineClearance [OnCopper and Not InComponentClass('Logo') and not InComponentClass('FiducialMark') and not InRegion(1000,500,4000,800) and not InPoly] p3: gap=19 ignorepadtopadclearanceinfootprint=FALSE
Clearance Clearance_2 [WithinRoom('Copper to PMIC IC')] p1: gap=5 ignorepadtopadclearanceinfootprint=FALSE except(0: Arc-Arc Arc-SMDPad Arc-Hole Track-Hole SMDPad-Hole THPad-Hole Via-Hole Fill-Hole Poly-Hole Region-Hole Text-Hole; 4: Arc-Track Track-Track; 4.5: Track-Via; 10: SMDPad-SMDPad)
Clearance Clearance_1 [All] p2: gap=15 ignorepadtopadclearanceinfootprint=FALSE except(0: Arc-SMDPad Arc-Hole Track-Hole SMDPad-Hole THPad-Hole Via-Hole Fill-Hole Poly-Hole Region-Hole Text-Hole; 5: Track-SMDPad; 5.6: Track-Region; 5.9: Via-Via; 6: Arc-Arc Arc-Track Arc-THPad Arc-Via Arc-Region Track-Track Track-THPad Track-Via SMDPad-SMDPad SMDPad-THPad SMDPad-Via SMDPad-Fill SMDPad-Poly THPad-THPad THPad-Via Via-Fill Via-Poly; 8: SMDPad-Region; 10: THPad-Fill THPad-Poly)
Clearance Clearance_Keepouts [((IsTrack Or IsArc) And Not InPoly) And IsFree and IsKeepOut vs ((IsTrack Or IsArc) And Not InPoly) And IsFree and IsKeepOut] p3: gap=0 ignorepadtopadclearanceinfootprint=FALSE
Clearance Clearance_Poly [InPolygon] p4: gap=25 ignorepadtopadclearanceinfootprint=FALSE except(0: Arc-Hole Track-Hole SMDPad-Hole THPad-Hole Via-Hole Fill-Hole Poly-Hole Region-Hole Text-Hole)
Clearance Clearance_FiducialMark [IsKeepOut and InComponentClass('FiducialMark') vs IsPad and InComponentClass('FiducialMark')] p5: gap=0 ignorepadtopadclearanceinfootprint=FALSE
Clearance [All] p6: gap=7.87 ignorepadtopadclearanceinfootprint=FALSE except(0: Arc-Hole Track-Hole SMDPad-Hole THPad-Hole Via-Hole Fill-Hole Poly-Hole Region-Hole Text-Hole)
ComponentClearance "Comp_Clr_Log3 to logo2" [InComponent('Logo3') vs InComponent('Logo2')] p1: gap=0 collisioncheckmode=3 verticalgap=0 showdistances=FALSE
ComponentClearance "Comp_Clr_Log1 to logo3" [InComponent('Logo1') vs InComponent('Logo3')] p2: gap=0 collisioncheckmode=3 verticalgap=0 showdistances=FALSE
ComponentClearance "Comp_Clr_361 to 362" [InComponent('R361') vs InComponent('R362')] p3: gap=0 collisioncheckmode=3 verticalgap=0 showdistances=FALSE
ComponentClearance "Comp_Clr_360 to 359" [InComponent('R359') vs InComponent('R360')] p4: gap=0 collisioncheckmode=3 verticalgap=0 showdistances=FALSE
ComponentClearance "Comp_Clr_357 to 358" [InComponent('R357') vs InComponent('R358')] p5: gap=0 collisioncheckmode=3 verticalgap=0 showdistances=FALSE
ComponentClearance "Comp_Clr_350 to 351" [InComponent('R350') vs InComponent('R351')] p6: gap=0 collisioncheckmode=3 verticalgap=0 showdistances=FALSE
ComponentClearance "Comp_Clr_349 to 347" [InComponent('R349') vs InComponent('R347')] p7: gap=0 collisioncheckmode=3 verticalgap=0 showdistances=FALSE
ComponentClearance Comp_Clr_J19 [InComponent('Logo3') vs InComponent('J19')] p8: gap=0 collisioncheckmode=3 verticalgap=0 showdistances=FALSE
ComponentClearance "Comp_Clr_J18 and J20" [InComponent('J18') vs InComponent('J20')] p9: gap=0 collisioncheckmode=3 verticalgap=0 showdistances=FALSE
ComponentClearance ComponentClearance_SMTtosmt [IsSMTComponent vs IsSMTComponent] p10: gap=10 collisioncheckmode=3 verticalgap=10 showdistances=FALSE
ComponentClearance ComponentClearance_MountingHoles_FiducialMarks [InComponentClass('Mounting Holes') vs InComponentClass('FiducialMark')] p11: gap=10 collisioncheckmode=3 verticalgap=15 showdistances=FALSE
ComponentClearance ComponentClearance_Shunt [InComponentClass('Header') vs InComponentClass('Shunt')] p12: gap=0 collisioncheckmode=3 verticalgap=0 showdistances=FALSE
ComponentClearance ComponentClearance_Logo [InComponentClass('Logo')] p13: gap=5 collisioncheckmode=3 verticalgap=5 showdistances=FALSE
ComponentClearance ComponentClearance_ScrewToNut [(HasFootprint('NY PMS 440 0025 PH')) vs (HasFootprint('Keystone_1902C'))] p14: gap=5 collisioncheckmode=3 verticalgap=10 showdistances=FALSE
ComponentClearance ComponentClearance_MountingHoles [InComponentClass('Mounting Holes')] p15: gap=50 collisioncheckmode=3 verticalgap=100000 showdistances=FALSE
ComponentClearance ComponentClearance_SmallPassives [HasFootprint('0201*') or HasFootprint('0402*') or HasFootprint('0508') or HasFootprint('0603*') or HasFootprint('0612') or HasFootprint('0805*') or HasFootprint('0815*') or HasFootprint('0830*') or HasFootprint('1206*') or HasFootprint('1210*') or HasFootprint('1808*') or HasFootprint('1812*') or HasFootprint('1825*') or HasFootprint('2010*') or HasFootprint('2220*') or HasFootprint('2225*') or HasFootprint('2512*') or HasFootprint('2728*') or HasFootprint('3518*') vs HasFootprint('0201*') or HasFootprint('0402*') or HasFootprint('0508') or HasFootprint('0603*') or HasFootprint('0612') or HasFootprint('0805*') or HasFootprint('0815*') or HasFootprint('0830*') or HasFootprint('1206*') or HasFootprint('1210*') or HasFootprint('1808*') or HasFootprint('1812*') or HasFootprint('1825*') or HasFootprint('2010*') or HasFootprint('2220*') or HasFootprint('2225*') or HasFootprint('2512*') or HasFootprint('2728*') or HasFootprint('3518*')] p16: gap=20 collisioncheckmode=3 verticalgap=20 showdistances=FALSE
ComponentClearance ComponentClearance_THtoSMT [IsThruComponent vs IsSMTComponent] p17: gap=10 collisioncheckmode=3 verticalgap=10 showdistances=FALSE
ComponentClearance ComponentClearance_THtoTH [IsThruComponent vs IsThruComponent] p18: gap=10 collisioncheckmode=3 verticalgap=10 showdistances=FALSE
ComponentClearance [All] p19: gap=10 collisioncheckmode=3 verticalgap=10 showdistances=TRUE
DiffPairsRouting 90OHM [InDifferentialPairClass('90ohm')] p1: maxlimit=6.01 minlimit=6.01 mostfreqgap=6.01 toplayer_minwidth=4.99 toplayer_maxwidth=4.99 toplayer_prefwidth=4.99 midlayer1_mingap=0 midlayer1_maxgap=0 midlayer1_prefgap=0 midlayer1_minwidth=0 midlayer1_maxwidth=0 midlayer1_prefwidth=0 midlayer2_minwidth=3.99 midlayer2_maxwidth=3.99 midlayer2_prefwidth=3.99 midlayer3_mingap=0 midlayer3_maxgap=0 midlayer3_prefgap=0 midlayer3_minwidth=0 midlayer3_maxwidth=0 midlayer3_prefwidth=0 midlayer4_minwidth=3.99 midlayer4_maxwidth=3.99 midlayer4_prefwidth=3.99 midlayer5_minwidth=3.99 midlayer5_maxwidth=3.99 midlayer5_prefwidth=3.99 midlayer6_mingap=0 midlayer6_maxgap=0 midlayer6_prefgap=0 midlayer6_minwidth=0 midlayer6_maxwidth=0 midlayer6_prefwidth=0 midlayer7_minwidth=3.99 midlayer7_maxwidth=3.99 midlayer7_prefwidth=3.99 midlayer8_mingap=0 midlayer8_maxgap=0 midlayer8_prefgap=0 midlayer8_minwidth=0 midlayer8_maxwidth=0 midlayer8_prefwidth=0 bottomlayer_minwidth=4.99 bottomlayer_maxwidth=4.99 bottomlayer_prefwidth=4.99 maxuncoupledlength=500
DiffPairsRouting 100OHM [InDifferentialPairClass('100ohm')] p2: maxlimit=11.99 minlimit=8.99 mostfreqgap=9.99 toplayer_maxgap=8.99 toplayer_prefgap=8.99 toplayer_minwidth=5.01 toplayer_maxwidth=5.01 toplayer_prefwidth=5.01 midlayer1_mingap=0 midlayer1_maxgap=0 midlayer1_prefgap=0 midlayer1_minwidth=0 midlayer1_maxwidth=0 midlayer1_prefwidth=0 midlayer2_mingap=11.99 midlayer2_prefgap=11.99 midlayer2_minwidth=4.01 midlayer2_maxwidth=4.01 midlayer2_prefwidth=4.01 midlayer3_mingap=0 midlayer3_maxgap=0 midlayer3_prefgap=0 midlayer3_minwidth=0 midlayer3_maxwidth=0 midlayer3_prefwidth=0 midlayer4_mingap=9.99 midlayer4_maxgap=9.99 midlayer4_minwidth=4.01 midlayer4_maxwidth=4.01 midlayer4_prefwidth=4.01 midlayer5_mingap=9.99 midlayer5_maxgap=9.99 midlayer5_minwidth=4.01 midlayer5_maxwidth=4.01 midlayer5_prefwidth=4.01 midlayer6_mingap=0 midlayer6_maxgap=0 midlayer6_prefgap=0 midlayer6_minwidth=0 midlayer6_maxwidth=0 midlayer6_prefwidth=0 midlayer7_mingap=11.99 midlayer7_prefgap=11.99 midlayer7_minwidth=4.01 midlayer7_maxwidth=11.99 midlayer7_prefwidth=4.01 midlayer8_mingap=0 midlayer8_maxgap=0 midlayer8_prefgap=0 midlayer8_minwidth=0 midlayer8_maxwidth=0 midlayer8_prefwidth=0 bottomlayer_maxgap=8.99 bottomlayer_prefgap=8.99 bottomlayer_minwidth=5.01 bottomlayer_maxwidth=5.01 bottomlayer_prefwidth=5.01 maxuncoupledlength=1000
FabricationTestPointUsage TestPointUsage [All] p1: valid=2 allowmultiple=FALSE
FabricationTestpoint Testpoint [All] p1: side=3 testpointundercomponent=TRUE minsize=40 maxsize=100 preferedsize=60 minholesize=0 maxholesize=40 preferedholesize=32 testpointgrid=1 allowsidetop=TRUE allowsidebottom=TRUE usegrid=TRUE gridtolerance=0.01
FanoutControl Fanout_LCC [IsLCC] p1: bgadir=Out bgaviamode=Centered fanoutstyle=Auto fanoutdirection=Alternating viagrid=1 // Fanout_LCC (Default Rule)
FanoutControl Fanout_BGA [IsBGA] p2: bgadir=Out bgaviamode=Centered fanoutstyle=Auto fanoutdirection=Alternating viagrid=1 // Fanout_BGA (Default Rule)
FanoutControl Fanout_Default [All] p4: bgadir=Out bgaviamode=Centered fanoutstyle=Auto fanoutdirection=Alternating viagrid=1 // Fanout_Default (Default Rule)
FanoutControl Fanout_Small [(CompPinCount < 5)] p5: bgadir=Out bgaviamode=Centered fanoutstyle=Auto fanoutdirection=OutThenIn viagrid=1 // Fanout_Small (Default Rule)
HoleSize [All] p1: absolutevalues=TRUE maxlimit=251 minlimit=7.87 maxpercent=80.000 minpercent=20.000
HoleToHoleClearance [All] p1: gap=8 allowstackedmicrovias=TRUE
MatchedLengths LVDS_phase [InDifferentialPairClass('100ohm')] p1: tolerance=10 checknetsindiffpair=TRUE checkdiffpairvsdiffpair=FALSE checkxsignals=FALSE checkothers=FALSE
MatchedLengths LVDS [InDifferentialPairClass('100ohm')] p2: tolerance=50 checknetsindiffpair=FALSE checkdiffpairvsdiffpair=TRUE checkxsignals=TRUE checkothers=TRUE
MatchedLengths Radar [InNetClass('Radar')] p3: tolerance=150 checknetsindiffpair=FALSE checkdiffpairvsdiffpair=TRUE checkxsignals=TRUE checkothers=TRUE
MatchedLengths SPI [InNetClass('SPI')] p4: tolerance=200 checknetsindiffpair=FALSE checkdiffpairvsdiffpair=TRUE checkxsignals=TRUE checkothers=TRUE
MinimumAnnularRing MinimumAnnularRing_ThermalPadVias [IsVia and InAnyComponent] p1: minimumring=3.9
MinimumAnnularRing [All] p2: minimumring=5.1
MinimumSolderMaskSliver MinimumSolderMaskSliver_Logo [InComponentClass('Logo') vs InComponentClass('Logo')] p1: minsoldermaskwidth=0.7
MinimumSolderMaskSliver [All] p2: minsoldermaskwidth=3.5
NetAntennae [All] p1: netantennaetolerance=4
PlaneConnect [All] p1: planeconnectstyle=Relief reliefexpansion=10 reliefentries=4 reliefconductorwidth=10 reliefairgap=10
PolygonConnect [All] p1: connectstyle=Direct reliefconductorwidth=10 reliefentries=4 polygonreliefangle="90 Angle" airgapwidth=10
RoutingVias ThermalPadVias [IsVia and InAnyComponent] p1: holewidth=12.2 width=22.4 viastyle="Through Hole" minholewidth=7.87 minwidth=15.75 maxholewidth=12.2 maxwidth=22.4
RoutingVias [All] p2: holewidth=12.2 width=22.4 viastyle="Through Hole" minholewidth=7.87 minwidth=15.75 maxholewidth=12.2 maxwidth=22.4
SilkToBoardRegionClearance [Not ((IsComment or IsDesignator) And (Hide <> 'False')) and not InRegion(1000,500,4000,800)] p1:
SilkToSilkClearance SilkToSilkClearance_Pb-FreeLogo [(HasFootprint('Pb-Free_Overlay_Medium') OR HasFootprint('Pb-Free_Overlay_Small')) vs (HasFootprint('Pb-Free_Overlay_Medium') OR HasFootprint('Pb-Free_Overlay_Small'))] p1: silktosilkclearance=0
SilkToSilkClearance [All] p2: silktosilkclearance=3
SilkToSolderMaskClearance SilkToComponentPadClearance [(IsPad or IsFill or IsRegion) and InAnycomponent] p1: minsilkscreentomaskgap=3 clearancetoexposedcopper=TRUE
SilkToSolderMaskClearance "Silk to Solder Mask Opening" [All] p2: minsilkscreentomaskgap=4 clearancetoexposedcopper=FALSE
SolderMaskExpansion [All] p1: expansion=0
Width pwr [InNetClass('PWR')] p1: maxlimit=100 minlimit=6 preferedwidth=10 checkconnectedcopper=TRUE
Width [All] p2: maxlimit=100 minlimit=4 preferedwidth=6 checkconnectedcopper=TRUE
13 further rules are at their usual default settings.

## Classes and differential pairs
component class PROC074A_XDS110_Interface_1B: C43 C44 C45 C46 C47 C48 R47 R48 R157 R158 R159 R160 R161 R162 R163 R164 R165 R166 R167 R168 R169 R170 U8 U9 Y1
component class PROC074A_XDS110_Interface_1A: C28 C29 C30 C32 C33 C34 C35 C36 C37 C38 C39 C40 C41 C42 J11 R147 R148 R149 R150 R152 R153 R154 R155 R156 U6 U7
component class PROC074A_Temp_Sensor: C49 C50 R171 R172 R173 R174 R175 R176 R177 R178 R179 R180 U18 U19
component class PROC074A_SOP_Selection: P4 P5 P6 R131 R132 R133 R134 R135 R136 R137 R138 R139 R140 R141 R142 R143
component class PROC074A_PWR_RST_LEDs: C22 C23 C24 D1 DS1 DS2 DS3 DS4 F1 FB1 FB2 P2 P3 P7 Q1 Q2 R51 R71 R74 R80 R114 R116 R117 R118 R119 R120 R121 R123 R124 R125 R126 R127 R128 R129 R130 SW1 SW2
component class PROC074A_PWR_INPUT_REG: C31 C78 C79 C80 C81 C82 C83 C84 C85 C86 C87 C89 C90 C91 C96 C97 C98 C99 C100 C101 C102 C103 C104 C105 C106 C107 C108 C109 C110 C111 C112 C113 D11 D14 J27 J28 L8 L9 R49 R50 R113 R115 R271 R272 R291 R293 R309 R312 R313 R315 R318 R326 R329 R363 R364 R367 R368 R369 R370 R403 R404 TP1 U13 U29 U31 U32
component class PROC074A_LP_Connector: J5 J6 J7 J8 R55 R56 R57 R58 R59 R60 R61 R64 R67 R70 R72 R75 R76 R77 R78 R79 R81 R82 R85 R86 R88 R89 R90 R91 R92 R93 R94 R95 R122 R224 R276 R393 R394
component class PROC074A_LP8752J_PMIC: C9 C10 C11 C12 C13 C14 C15 C16 C17 C18 C19 C20 C21 L1 L2 L3 L4 R97 R98 R99 R100 R101 R102 R103 R104 R105 R106 R107 R108 R109 R110 R111 R112 R286 R287 R288 R289 R399 R400 R401 R402 U4
component class PROC074A_HD_Connector_DCA: J9 J10 R20 R21 R27 R28 R29 R30 R54 R96 R144 R145 R146 R229 R230 R231 R235 R236 R237 R238 R239 R240 R241 R242 R243 R244 R245 R246 R268 R269 R270
component class PROC074A_HD_Conn_JTAG_HDR: C117 J3 J4 J17 J18 J19 J20 R14 R34 R35 R36 R37 R38 R39 R40 R41 R42 R44 R45 R46 R52 R53 R232 R233 R234 R273 R294 R295 R296 R297 R298 U36
component class PROC074A_FTDI_Interface: C51 C52 C53 C54 C56 C57 C58 C59 C60 C61 D4 L5 L6 R43 R182 R183 R184 R188 R189 R190 R191 R192 R194 R195 R196 R197 R198 R199 R200 R201 R202 R204 R205 R206 R207 R208 R210 R211 R212 R213 R214 R215 R216 R217 R218 U15 Y2
component class PROC074A_FTDI_Interface_PWR: C55 C62 C63 C64 C65 C66 C67 C68 C69 C70 J12 J13 R181 R185 R186 R187 R193 R219 R220 R221 R222 R223 R225 R226 R227 R228 R290 U14 U16 U17
component class PROC074A_Current_Sensors: C6 C7 C8 C25 C26 R299 R301 R303 R304 R305 R306 R307 R308 R310 R311 R314 R316 R317 R319 R320 R321 R322 R323 R324 R325 R327 R328 R330 R331 R332 U11 U20 U21 U22 U23
component class PROC074A_CAN_Interface: C1 C2 C3 C4 C88 C119 C120 J1 P1 R1 R2 R3 R4 R5 R6 R7 R8 R260 R261 R395 R396 R397 U1 U2 U30
component class PROC074A_CAN_Interface_LEDs: C5 C71 C74 C75 C76 C77 D5 D6 D7 D8 D9 D10 J2 L7 R10 R11 R12 R15 R31 R32 R33 R251 R252 R253 R254 R255 R256 U3 U12
component class PROC074A_BP_LP_RNR_Options: J16 R9 R13 R22 R69 R73 R247 R248 R249 R274 R275 R281 R283 R346 R347 R348 R349 R350 R351 R353 R354 R356 R357 R358 R359 R360 R361 R362 R398
component class PROC074A_Analog_Mux_1B: C95 C114 C115 C116 J14 J15 R18 R19 R23 R24 R62 R65 R68 R262 S1 U28 U33 U34 U35
component class PROC074A_Analog_Mux_1A: C27 C72 C73 C92 C93 C94 R16 R17 R25 R26 R63 R66 R151 R203 R209 R250 R338 R339 U5 U10 U24 U25 U26 U27
component class Header: J13 J14 J15 J16 J18 J19 J20 J27 J28 P1 P3 P4 P5 P6 P7
component class Logo: Logo1
component class PROC074A_EVM_Hardware: "CAUTION HOT SURFACE1" FID1 FID2 FID3 FID4 FID5 FID6 LBL1 Logo1 Logo2 Logo3 Logo4 ZZ1 ZZ2 ZZ3 ZZ4
component class FiducialMark: FID1 FID2 FID3 FID4 FID5 FID6
component class AssemblyNote: ZZ1 ZZ2 ZZ3 ZZ4
component class Label: LBL1
net class Radar: RADAR_DP0 RADAR_DP1 RADAR_DP2 RADAR_DP3 RADAR_DP4 RADAR_DP5 RADAR_DP6 RADAR_DP7 RADAR_DP8 RADAR_DP9 RADAR_DP10 RADAR_DP11 RADAR_DP12 RADAR_DP13 RADAR_DP14 RADAR_DP15
net class LVDS: RADAR_LVDS_0M RADAR_LVDS_0P RADAR_LVDS_1M RADAR_LVDS_1P RADAR_LVDS_2M RADAR_LVDS_2P RADAR_LVDS_3M RADAR_LVDS_3P RADAR_LVDS_CLKM RADAR_LVDS_CLKP RADAR_LVDS_FRCLKM RADAR_LVDS_FRCLKP RADAR_LVDS_VALIDM RADAR_LVDS_VALIDP
net class PWR: 5V_IN BOOST_3V3_IN BP_LP_3V3 BRD_3V3 CB_PMIC_1V0 CB_PMIC_1V2 CB_PMIC_1V8 FPWM1 FPWM2 FTDI_3V3 FTDI_VBUS FTDI_VCORE GND MCU_3V3 MCU_5V NetC1_2 NetC22_1 NetC74_1 NetC96_2 NetD1_1 NetF1_2 NetJ10_1 PMIC_1V0 PMIC_1V2 PMIC_1V8 PMIC_3V3 PMICVIO_3V3 UNREG_IN1 UNREG_IN2 VBOOST_5V VCC_3V3 VCC_XDS_3V3 VDDC_1 VLDO_3V3 VPP_1P7 WIDE_IN_5V_OP XDSET_1_VBUS
net class SPI: 40PIN_CS1 40PIN_MISO1 40PIN_MOSI1 40PIN_SPI_CLK1 60PIN_CS1 60PIN_MISO1 60PIN_MOSI1 60PIN_SPICLK1 FTDI_CLK1 FTDI_CS1 FTDI_MISO1 FTDI_MOSI1 MUX_CS1 MUX_MISO1 MUX_MOSI1 MUX_SPI_CLK1 RADAR_SPI_CLK1 RADAR_SPI_CS1 RADAR_SPI_MISO1 RADAR_SPI_MOSI1 SPI_CLK1 SPI_CS1 SPI_MISO1 SPI_MOSI1
differential pair class 100ohm: D_RADAR_LVDS_0 D_RADAR_LVDS_1 D_RADAR_LVDS_2 D_RADAR_LVDS_3 D_RADAR_LVDS_CLK D_RADAR_LVDS_FRCLK D_RADAR_LVDS_VALID
differential pair class 90ohm: D_USBD D_XDSET_1_D
differential pair D_RADAR_LVDS_0: +RADAR_LVDS_0M -RADAR_LVDS_0P
differential pair D_RADAR_LVDS_1: +RADAR_LVDS_1M -RADAR_LVDS_1P
differential pair D_RADAR_LVDS_2: +RADAR_LVDS_2M -RADAR_LVDS_2P
differential pair D_RADAR_LVDS_3: +RADAR_LVDS_3M -RADAR_LVDS_3P
differential pair D_RADAR_LVDS_CLK: +RADAR_LVDS_CLKM -RADAR_LVDS_CLKP
differential pair D_RADAR_LVDS_FRCLK: +RADAR_LVDS_FRCLKM -RADAR_LVDS_FRCLKP
differential pair D_RADAR_LVDS_VALID: +RADAR_LVDS_VALIDM -RADAR_LVDS_VALIDP
differential pair D_USBD: +USBDM -USBDP
differential pair D_XDSET_1_D: +XDSET_1_DM -XDSET_1_DP

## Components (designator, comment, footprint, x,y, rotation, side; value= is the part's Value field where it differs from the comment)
C1 "C0402C104K8RACTU" 0402L 1495,1880 r90 bottom value=0.1uF
C2 "C0402C104K8RACTU" 0402L 1305,1990 r0 top value=0.1uF
C3 "C1005X7R1H472K050BA" 0402L 2387.09,1612.3 r0 top value=4700pF
C4 "C0402C104K8RACTU" 0402 2225,1885 r180 top value=0.1uF
C5 "C1005X7R1H472K050BA" 0402 1536.81,1628.78 r270 bottom value=4700pF
C6 "CGA2B3X7R1H104K050BB" 0402L 2275.32,1605 r180 bottom value=0.1uF
C7 "CGA2B3X7R1H104K050BB" 0402L 1642.37,2634.06 r90 top value=0.1uF
C8 "CGA2B3X7R1H104K050BB" 0402L 1984.37,1514.06 r180 bottom value=0.1uF
C9 "GCM21BR71A106KE22L" 0805_HV 1785.22,2227.46 r180 bottom value=10uF
C10 "GCM21BR71A106KE22L" 0805_HV 1931.22,2227.46 r0 bottom value=10uF
C11 "GCM21BR71A106KE22L" 0805_HV 1785.22,1831.32 r180 bottom value=10uF
C12 "GCM21BR71A106KE22L" 0805_HV 1933.22,1831.46 r0 bottom value=10uF
C13 "GCM31CR71A226KE02" 1206_180 1815.88,2387.1 r90 bottom value=22uF
C14 "GCM31CR71A226KE02" 1206_180 1904.88,2386.1 r90 bottom locked value=22uF
C15 "GCM31CR71A226KE02" 1206_180 1812.7,1672.1 r270 bottom value=22uF
C16 "GCM31CR71A226KE02" 1206_180 1904.7,1674.1 r270 bottom value=22uF
C17 "GCM155R71C224KE02D" 0402L 2022.22,2038.46 r180 bottom value=0.22uF
C18 "CGA2B2NP01H391J050BA" 0402L 1658.54,2210.38 r270 bottom value=390pF
C19 "CGA2B2NP01H391J050BA" 0402L 2066.22,2229.46 r270 bottom value=390pF
C20 "CGA2B2NP01H391J050BA" 0402L 1654.22,1837.15 r90 bottom value=390pF
C21 "CGA2B2NP01H391J050BA" 0402L 2068.22,1839.46 r90 bottom value=390pF
C22 "597D476X9050Z2T" 597D_Z 2279.37,259.06 r270 top value=47uF
C23 "597D476X9050Z2T" 597D_Z 2004.37,259.06 r270 top value=47uF
C24 "GCM155R71C104KA55D" 0402L 2595.37,2038.06 r90 bottom value=0.1uF
C25 "CGA2B3X7R1H104K050BB" 0402L 1904.09,2646.69 r90 bottom value=0.1uF
C26 "CGA2B3X7R1H104K050BB" 0402L 1689.22,1497.52 r90 top value=0.1uF
C27 "C0402C104K8RACTU" 0402 790,2330 r0 top value=0.1uF
C28 "CL10B105KQ8NNNC" 0603 900.37,2666.8 r270 bottom value=1uF
C29 "GRM188R70J104KA01D" 0603 912.37,2965 r90 bottom value=0.1uF
C30 "CGA2B3X7S2A102K050BB" 0402 807.1,2956.6 r90 bottom value=1000pF
C31 "GCM188R71C105KA64D" 0603 569,1069 r270 bottom value=1uF
C32 "C0402C104K8RACTU" 0402L 1615.49,2888.76 r90 bottom value=0.1uF
C33 "C0402C104K8RACTU" 0402L 1306.37,2879.06 r90 bottom value=0.1uF
C34 "C0402C104K8RACTU" 0402L 1277.37,3692.06 r180 bottom value=0.1uF
C35 "C1005X7S0J105M050BC" 0402L 1435.49,3674.16 r270 bottom value=1uF
C36 "C0402C104K8RACTU" 0402L 966.8,3243.99 r0 top value=0.1uF
C37 "C1005X7S0J105M050BC" 0402L 1031.37,3111.06 r90 bottom value=1uF
C38 "C1005X7R1E103K050BB" 0402L 1210.37,2890.06 r0 bottom value=0.01uF
C39 "C1005X7S1A225K050BC" 0402_065L 1820.49,3303.76 r270 bottom value=2.2uF
C40 "C0402C104K8RACTU" 0402L 1775.49,3303.76 r270 bottom value=0.1uF
C41 "C1005X7S0J105M050BC" 0402L 1345.37,2879.06 r90 bottom value=1uF
C42 "C0402C103K4RACTU" 0402L 2505.22,3432.34 r180 top value=0.01uF
C43 "C0402C104K8RACTU" 0402L 1715.49,2923.76 r90 bottom value=0.1uF
C44 "C0402C104K8RACTU" 0402L 1770.49,3478.76 r270 bottom value=0.1uF
C45 "C0402C104K8RACTU" 0402L 960,3115 r0 bottom value=0.1uF
C46 "C0402C103K4RACTU" 0402L 953.17,3169.06 r0 bottom value=0.01uF
C47 "GRM1555C1H8R0DA01D" 0402L 1895,3065 r90 bottom value=8pF
C48 "GRM1555C1H8R0DA01D" 0402L 1838,3246 r180 bottom value=8pF
C49 "C0402C104K8RACTU" 0402L 1640.09,2002.2 r90 top value=0.1uF
C50 "C0402C104K8RACTU" 0402L 334.43,2227.8 r90 top value=0.1uF
C51 "C1608X7S1A475K080AC" 0603 1675,3105 r0 top value=4.7uF
C52 "C0402C104K8RACTU" 0402 1665,3160 r180 top value=0.1uF
C53 "C1608X7S1A475K080AC" 0603 1719.85,3339.59 r90 top value=4.7uF
C54 "C0402C104K8RACTU" 0402 1659.85,3329.59 r270 top value=0.1uF
C55 "C0402C104K8RACTU" 0402 1835,2790 r180 top value=0.1uF
C56 "C0402C104K8RACTU" 0402 1607.78,3329.18 r270 top value=0.1uF
C57 "C0402C104K8RACTU" 0402 1496.69,2971.95 r0 top value=0.1uF
C58 "C1608X7S1A475K080AC" 0603 971.5,2985 r180 top value=4.7uF
C59 "C0402C104K8RACTU" 0402 975,3040 r180 top value=0.1uF
C60 "GRM1555C1H8R0DA01D" 0402 1800,2978 r0 top value=8pF
C61 "GRM1555C1H8R0DA01D" 0402 1805,2924 r0 top value=8pF
C62 "C1005X7S1A225K050BC" 0402_065 1184.37,2720.06 r180 top value=2.2uF
C63 "C0402C104K8RACTU" 0402 2431.37,4033.95 r180 bottom value=0.1uF
C64 "04025A150FAT2A" 0402 1275.51,2651.19 r270 bottom value=15pF
C65 "C1005X7S1A225K050BC" 0402_065 1230,2621.38 r270 top value=2.2uF
C66 "GCM188R71C105KA64D" 0603 1422.78,3614.18 r90 top value=1uF
C67 "C0402C104K8RACTU" 0402 1162.78,3604.18 r90 top value=0.1uF
C68 "C0402C104K8RACTU" 0402 1334.37,2966.18 r0 top value=0.1uF
C69 "GCM188R71C105KA64D" 0603 1100,2910 r270 top value=1uF
C70 "C0402C104K8RACTU" 0402 1189.16,2969.18 r0 top value=0.1uF
C71 "CGA2B3X7R1H104K050BB" 0402 1457.26,1501.13 r180 bottom value=0.1uF
C72 "C0402C104K8RACTU" 0402 474.37,2154.68 r90 top value=0.1uF
C73 "C0402C104K8RACTU" 0402 785.63,2482 r0 top value=0.1uF
C74 "CGA2B3X7R1H104K050BB" 0402 1246.81,1623.78 r90 bottom value=0.1uF
C75 "C0603C225K8PACTU" 0603 992.37,1700.06 r270 bottom value=2.2uF
C76 "C0603C225K8PACTU" 0603 1107.13,1765.91 r180 bottom value=2.2uF
C77 "CGA2B3X7R1H104K050BB" 0402 1114.62,1756.53 r180 top value=0.1uF
C78 "JMK105B7474KVHF" 0402 2154.37,1089.06 r90 top value=0.47uF
C79 "EEE-FK1H100UR" SM_RADIAL_C 2204.37,571.14 r0 top value=10uF
C80 "GRM32ER71H106MA12" 1210_270 2079.37,744.06 r0 top value=10uF
C81 "C1210C104K5RACTU" 1210 2079.37,879.06 r0 top value=0.1uF
C82 "C0805C103K5RACTU" 0805_HV 2069.37,989.06 r0 top value=0.01uF
C83 "GRM32ER71H106MA12" 1210_270 2151.37,1560.06 r0 top value=10uF
C84 "C1210C104K5RACTU" 1210 2150.37,1435.06 r0 top value=0.1uF
C85 "C0805C103K5RACTU" 0805_HV 2090.37,1318.06 r0 top value=0.01uF
C86 "0402YC104KAT2A" 0402 1859.37,1154.06 r90 top value=0.1uF
C87 "C2012X7R1E475K125AB" 0805_HV 1879.37,1024.06 r180 top value=4.7uF
C88 "C1005X7S1A225K050BC" 0402_065L 732.41,1215 r0 top value=2.2uF
C89 "CL32B226KOJNFNE" 1210_270 2244.37,979.06 r270 top value=22uF
C90 "CL32B226KOJNFNE" 1210_270 2379.37,979.06 r270 top value=22uF
C91 "CL32B226KOJNFNE" 1210_270 2364.37,1419.06 r90 top value=22uF
C92 "C0402C104K8RACTU" 0402 1520.04,2533.13 r0 bottom value=0.1uF
C93 "C0402C104K8RACTU" 0402 1310.37,2418.06 r180 bottom value=0.1uF
C94 "C0402C104K8RACTU" 0402 728.37,2141.06 r180 top value=0.1uF
C95 "C0402C104K8RACTU" 0402 1360,2220 r0 bottom value=0.1uF
C96 "JMK105B7474KVHF" 0402 1479.37,1134.06 r90 top value=0.47uF
C97 "EEE-FK1H100UR" SM_RADIAL_C 1679.37,854.06 r270 top value=10uF
C98 "GRM32ER71H106MA12" 1210_270 1082,1020.03 r90 top value=10uF
C99 "C1210C104K5RACTU" 1210 944.37,1019.06 r90 top value=0.1uF
C100 "C0805C103K5RACTU" 0805_HV 1194.37,1004.06 r90 top value=0.01uF
C101 "GRM32ER71H106MA12" 1210_270 1599.37,1119.06 r90 top value=10uF
C102 "C1210C104K5RACTU" 1210 1724.37,1119.06 r90 top value=0.1uF
C103 "C0805C103K5RACTU" 0805_HV 1484.37,999.06 r90 top value=0.01uF
C104 "0402YC104KAT2A" 0402 1349.37,819.06 r180 top value=0.1uF
C105 "CL32B226KOJNFNE" 1210_270 1237.53,1419.87 r90 top value=22uF
C106 "CL32B226KOJNFNE" 1210_270 1549.37,1314.06 r0 top value=22uF
C107 "CL32B226KOJNFNE" 1210_270 1372.99,1420.82 r90 top value=22uF
C108 "C2012X7R1E475K125AB" 0805_HV 1469.37,839.06 r270 top value=4.7uF
C109 "C0603C104J3RACTU" 0603 532.7,904.23 r180 top value=0.1uF
C110 "CGA2B3X7S2A102K050BB" 0402 564.7,980.09 r0 bottom value=1000pF
C111 "GCM188R71C105KA64D" 0603 643.37,1678.06 r270 top value=1uF
C112 "C0603C104J3RACTU" 0603 550.37,1990.55 r90 top value=0.1uF
C113 "CGA2B3X7S2A102K050BB" 0402 737.99,1815.06 r180 bottom value=1000pF
C114 "C0402C104K8RACTU" 0402 1450,2057 r0 bottom value=0.1uF
C115 "C0402C104K8RACTU" 0402 1281.37,2054.06 r180 bottom value=0.1uF
C116 "C0402C104K8RACTU" 0402 849.75,1890.06 r180 bottom value=0.1uF
C117 "C0402C104K8RACTU" 0402 765.61,2001.06 r90 top value=0.1uF
C119 "C0402C330J5GAC" 0402L 746.63,1428 r180 bottom value=33pF
C120 "C1005X7S0J105M050BC" 0402L 742.53,1392.79 r0 top value=1uF
"CAUTION HOT SURFACE1" "CAUTION HOT SURFACE" IEC_HotSurface_Small 2183,2649.66 r0 top
D1 "SMBJ30A-13-F" SMB 2166,109 r180 bottom value=30V
D4 "TLMY1000-GS08" TLMx1000_Yellow 2596.57,4265.06 r0 top value=Yellow
D5 "TLMY1000-GS08" TLMx1000_Yellow 761,118.11 r270 top value=Yellow
D6 "TLMY1000-GS08" TLMx1000_Yellow 829.95,118.11 r270 top value=Yellow
D7 "TLMY1000-GS08" TLMx1000_Yellow 898.94,118.11 r270 top value=Yellow
D8 "TLMS1000-GS08" TLMx1000_Red 970,118.11 r270 top value=Red
D9 "TLMS1000-GS08" TLMx1000_Red 2619.86,4338.43 r180 top value=Red
D10 "TLMS1000-GS08" TLMx1000_Red 693,118.11 r270 top value=Red
D11 "SML-P12PTT86" SML-P1_GREEN 2572.7,744.06 r270 top value=Green
D14 "SML-P12PTT86" SML-P1_GREEN 2644.37,744.06 r270 top value=Green
Designator1 "Comment" STANDOFF_FAB_0022 1476.38,250 r180 bottom locked
DS1 "TLMY1000-GS08" TLMx1000_Yellow 2655,1795 r180 top value=Yellow
DS2 "TLMY1000-GS08" TLMx1000_Yellow 2685,4445 r90 top value=Yellow
DS3 "TLMS1000-GS08" TLMx1000_Red 624,118.11 r270 top value=Red
DS4 "TLMS1000-GS08" TLMx1000_Red 554,118.11 r270 top value=Red
F1 "0440005.WR" 1206 2474.37,174.06 r90 top
FB1 "BLM21PG300SH1D" 0805_HV 2269.37,329.06 r90 bottom value="30 ohm"
FB2 "BLM21PG300SH1D" 0805_HV 2359.37,329.06 r90 bottom value="30 ohm"
FID1 "Fiducial" Fiducial10-20 2572,4917 r0 top
FID2 "Fiducial" Fiducial10-20 137,4846 r180 bottom
FID3 "Fiducial" Fiducial10-20 2572,4917 r90 bottom
FID4 "Fiducial" Fiducial10-20 137,4846 r90 top
FID5 "Fiducial" Fiducial10-20 96,112 r90 top
FID6 "Fiducial" Fiducial10-20 96,112 r90 bottom
J1 "OSTTE030161" On-Shore_OSTTE030161 2595,1490 r90 top
J2 "OSTTE030161" On-Shore_OSTTE030161 2595,1045 r90 top
J3 "128-0711-201" Johnson_128-0711-201 2570,4645 r90 top
J4 "QTH-030-01-L-D-A" Samtec_QTH-030-01-x-D-A 1960,4340.95 r90 top locked
J5 "SSM-110-S-DV" Samtec_SSM-110-x-DV 418.85,3193 r270 bottom locked
J6 "SSM-110-S-DV" Samtec_SSM-110-x-DV 2118.85,3193 r270 bottom locked
J7 "SSM-103-S-SV" Samtec_SSM-103-x-SV 377.61,2443 r270 bottom
J8 "SSM-103-S-SV" Samtec_SSM-103-x-SV 2160.09,2443 r270 bottom
J9 "QSH-030-01-L-D-A" Samtec_QSH-030-01-X-D-A 256.37,1582.06 r180 top
J10 "QSH-030-01-L-D-A" Samtec_QSH-030-01-X-D-A 516.3,2960.59 r0 top
J11 "105017-0001" CONN_105017-0001 2645.84,3279.39 r270 bottom
J12 "105017-0001" CONN_105017-0001 2645.84,3954.39 r270 bottom
J13 "22284033" Molex_0022284033 990,2720 r90 top
J14 "22284033" Molex_0022284033 2382.37,2974.06 r270 bottom
J15 "22284033" Molex_0022284033 1869.37,3589.06 r90 bottom
J16 "TSW-105-07-G-D" TSW-105-07-G-D 705,385 r0 top
J17 "QTH-030-01-L-D-A" Samtec_QTH-030-01-x-D-A 668.5,4340.95 r270 top
J18 "TSW-108-07-G-D" TSW-108-07-G-D 705,607 r0 top
J19 "TSW-107-07-L-D-006" Samtec_TSW-107-07-L-D-006 2607,2641 r180 top
J20 "TSW-108-07-G-D" TSW-108-07-G-D 1515,602 r0 top
J27 "22284033" Molex_0022284033 813,1011 r270 top
J28 "22284033" Molex_0022284033 879.37,1604.06 r270 top
L1 "DFE252012P-R47M=P2" DFE252012P 1720.88,2333.46 r90 bottom value=470nH
L2 "DFE252012P-R47M=P2" DFE252012P 2003.22,2333.46 r90 bottom value=470nH
L3 "DFE252012P-R47M=P2" DFE252012P 1714.65,1725.46 r270 bottom value=470nH
L4 "DFE252012P-R47M=P2" DFE252012P 2004.22,1725.46 r270 bottom value=470nH
L5 "BLM15HG601SN1D" 0402 1680,3050 r180 top value="600 ohm"
L6 "BLM15HG601SN1D" 0402 1779.85,3334.59 r270 top value="600 ohm"
L7 "LQM21PN1R0MC0D" 0805_HV 993.37,1706.06 r90 top value=1uH
L8 "XAL5030-222MEB" XAL5030 2304.37,1199.06 r0 top value=2.2uH
L9 "XAL5030-222MEB" XAL5030 1334.37,1199.06 r90 top value=2.2uH
LBL1 "THT-14-423-10" Label_650x200 1609,4377 r90 top
Logo1 "Texas Instruments" TI_Stacked_Overlay_Small 463,3648 r0 top
Logo2 "CE Mark" CE_Mark_5mm 214,2446 r0 top
Logo3 "FCC disclaimer" FCC_disclaimer 2708,2999 r90 top
Logo4 "WEEE logo" WEEE_Minimum 2400,3675 r0 top
MH1 "Comment" MTGNP431H431 136,5170 r0 top locked
MH2 "Comment" MTGNP431H431 2365,5190 r0 top locked
MH3 "Comment" MTGNP431H431 132.9,2146.53 r0 top locked
MH4 "Comment" MTGNP431H431 2372.9,2146.53 r0 top locked
P1 "TSW-102-07-G-S" TSW-102-07-X-S 895.63,1336 r90 top
P2 "PJ-002AH" CUI_PJ-002AH 2576.85,459.02 r0 top
P3 "TSW-102-07-G-S" TSW-102-07-X-S 1994.37,574.06 r270 top
P4 "TSW-102-07-G-S" TSW-102-07-X-S 148.37,676.66 r180 top
P5 "TSW-102-07-G-S" TSW-102-07-X-S 148.37,476.8 r180 top locked
P6 "TSW-102-07-G-S" TSW-102-07-X-S 148.37,279.06 r180 top
P7 "TSW-102-07-G-S" TSW-102-07-X-S 1889.37,819.06 r270 top
Q1 "BSS123" SOT-23 2505.37,1786.06 r0 top locked value=100V
Q2 "BSS123" SOT-23 2565,4475 r0 top value=100V
R1 "ERJ-2GE0R00X" 0402 1624,1836.85 r270 top value=0
R2 "CRCW040261R9FKED" 0402L 2408,1485 r0 bottom value=61.9
R3 "ERJ-2GE0R00X" 0402L 1575,1835.85 r270 top value=0
R4 "CRCW040210K0FKED" 0402L 1520,1825 r0 bottom value=10.0k
R5 "CRCW040210K0FKED" 0402L 1530,1880 r270 bottom value=10.0k
R6 "ERJ-2GE0R00X" 0402 1603,1753.85 r180 top value=0
R7 "CRCW040261R9FKED" 0402L 2408,1525 r180 bottom value=61.9
R8 "ERJ-2GE0R00X" 0402 1596,1931.85 r180 top value=0
R9 "CRCW040210K0FKED" 0402 1923.63,4642 r90 bottom value=10.0k
R10 "ERJ-2GEJ511X" 0402 761.6,217.3 r270 top value=510
R11 "CRCW040261R9FKED" 0402 1458.17,1649.28 r180 bottom value=61.9
R12 "ERJ-2GE0R00X" 0402 1458.17,1699.28 r0 bottom value=0
R13 "CRCW040210K0FKED" 0402 1949.63,4538.38 r270 bottom value=10.0k
R14 "CRCW02010000Z0ED" 0201_Silk 2460,4632.01 r90 top value=0
R15 "ERJ-2GE0R00X" 0402 1458.17,1549.28 r0 bottom value=0
R16 "CRCW04024K70JNED" 0402 543.87,2155.06 r270 top value=4.7k
R17 "CRCW04024K70JNED" 0402 783.63,2524 r180 bottom locked value=4.7k
R18 "CRCW040210K0FKED" 0402L 1305,2141.06 r0 top value=10.0k
R19 "CRCW040210K0FKED" 0402L 1298.73,2055 r0 top value=10.0k
R20 "ERJ-2GE0R00X" 0402 528.26,1343.95 r180 top value=0
R21 "ERJ-2GE0R00X" 0402 528.26,1393.95 r180 top value=0
R22 "CRCW040210K0FKED" 0402 2069.01,4516.99 r180 bottom value=10.0k
R23 "CRCW040210K0FKED" 0402L 873.1,1945 r180 bottom value=10.0k
R24 "CRCW040210K0FKED" 0402L 1267,2240 r90 top value=10.0k
R25 "CRCW040210K0FKED" 0402L 837.37,2164.37 r90 top value=10.0k
R26 "CRCW040210K0FKED" 0402L 784.63,2482 r180 bottom value=10.0k
R27 "ERJ-2GE0R00X" 0402 528.26,1443.95 r180 top value=0
R28 "ERJ-2GE0R00X" 0402 528.26,1493.95 r180 top value=0
R29 "ERJ-2GE0R00X" 0402 528.26,1548.95 r180 top value=0
R30 "ERJ-2GE0R00X" 0402 528.26,1598.95 r180 top value=0
R31 "CRCW040261R9FKED" 0402 1458.17,1599.28 r0 bottom value=61.9
R32 "ERJ-2GE0R00X" 0402 1266.81,1543.78 r180 bottom value=0
R33 "ERJ-2GE0R00X" 0402 1301.81,1623.78 r270 bottom value=0
R34 "ERJ-2GEJ101X" 0402 2476.37,2487.43 r270 bottom value=100
R35 "ERJ-2GE0R00X" 0402 617,773 r270 bottom value=0
R36 "ERJ-2GE0R00X" 0402 567,773 r90 bottom value=0
R37 "CRCW040210K0FKED" 0402L 832.96,2043.11 r90 bottom value=10.0k
R38 "ERJ-2GE0R00X" 0402 723.19,771.65 r270 bottom value=0
R39 "ERJ-2GE0R00X" 0402 668.19,771.65 r90 bottom value=0
R40 "ERJ-2GE0R00X" 0402 789.37,769.06 r270 bottom value=0
R41 "CRCW04024K70JNED" 0402 834.37,2041.06 r90 top value=4.7k
R42 "ERJ-2GE0R00X" 0402 849.37,769.06 r90 bottom value=0
R43 "ERJ-2GE0R00X" 0402 977.37,3349.06 r180 bottom value=0
R44 "ERJ-2GE0R00X" 0402 2467.37,2755.06 r270 bottom value=0
R45 "ERJ-2GE0R00X" 0402 949.37,772.68 r270 bottom value=0
R46 "ERJ-2GE0R00X" 0402 1004.37,772.68 r90 bottom value=0
R47 "ERJ-2GE0R00X" 0402 1499.37,2875.06 r180 bottom value=0
R48 "ERJ-2GE0R00X" 0402 1421.37,2860.06 r90 bottom value=0
R49 "PMR18EZPFV2L00" 1206 611.37,1189.06 r180 bottom value=0.002
R50 "PMR18EZPFV2L00" 1206 519.37,1748.06 r90 bottom value=0.002
R51 "CRCW040210K0FKED" 0402L 2665,2235 r180 bottom value=10.0k
R52 "ERJ-2GE0R00X" 0402 1166.37,736.85 r0 bottom value=0
R53 "ERJ-2GE0R00X" 0402 1057.15,771.65 r90 bottom value=0
R54 "ERJ-2GE0R00X" 0402 528.26,1803.95 r180 top value=0
R55 "CRCW0402100KFKED" 0402L 187,3443 r180 bottom value=100k
R56 "CRCW0402100KFKED" 0402L 186.32,3342 r180 bottom value=100k
R57 "CRCW040210K0FKED" 0402L 202.06,2808.06 r0 bottom value=10.0k
R58 "CRCW040210K0FKED" 0402L 200.37,2702.06 r0 bottom value=10.0k
R59 "CRCW20100000Z0EF" 2010 756.37,3616.06 r0 bottom value=0
R60 "CRCW040210K0FKED" 0402L 2010,3500 r0 top value=10.0k
R61 "CRCW040210K0FKED" 0402L 2010,3095 r0 top value=10.0k
R62 "CRCW04024K70JNED" 0402 1455.59,2130.24 r180 bottom value=4.7k
R63 "CRCW04024K70JNED" 0402 808.26,2399.95 r180 bottom value=4.7k
R64 "CRCW0402100KFKED" 0402L 2227,3401 r180 top value=100k
R65 "CRCW04024K70JNED" 0402 1201.75,1967.06 r0 bottom value=4.7k
R66 "CRCW04024K70JNED" 0402 1519.93,2599.87 r180 bottom value=4.7k
R67 "CRCW02010000Z0ED" 0201_Silk 2144.37,3644.06 r180 top value=0
R68 "CRCW04024K70JNED" 0402 913.37,1838.06 r0 bottom value=4.7k
R69 "CRCW040210K0FKED" 0402 2090.01,4141.99 r180 bottom value=10.0k
R70 "CRCW02010000Z0ED" 0201_Silk 2007.63,3543 r0 top value=0
R71 "CRCW040210K0FKED" 0402L 2570,2235 r0 bottom value=10.0k
R72 "CRCW02010000Z0ED" 0201_Silk 2230.07,3443 r0 top value=0
R73 "CRCW0402100KFKED" 0402L 1720.37,4756.06 r180 bottom value=100k
R74 "ERJ-2GE0R00X" 0402L 2665,2200 r0 bottom value=0
R75 "ERJ-2GE0R00X" 0402 160,3227 r180 bottom value=0
R76 "CRCW02010000Z0ED" 0201_Silk 2224.37,3359.06 r0 top value=0
R77 "CRCW02010000Z0ED" 0201_Silk 183.36,3044.06 r0 bottom value=0
R78 "CRCW02010000Z0ED" 0201_Silk 2230.07,3243 r180 top value=0
R79 "CRCW02010000Z0ED" 0201_Silk 187.38,2941.06 r0 bottom value=0
R80 "ERJ-2GE0R00X" 0402L 2570,2200 r180 bottom value=0
R81 "CRCW02010000Z0ED" 0201_Silk 2007.63,3243 r180 top value=0
R82 "CRCW02010000Z0ED" 0201_Silk 198.37,2844.06 r0 bottom value=0
R85 "CRCW02010000Z0ED" 0201_Silk 2228.36,3144.06 r180 top value=0
R86 "CRCW02010000Z0ED" 0201_Silk 196.37,2742.06 r0 bottom value=0
R88 "CRCW02010000Z0ED" 0201_Silk 1909.37,2972.05 r90 bottom value=0
R89 "CRCW02010000Z0ED" 0201_Silk 2235,3030 r0 top value=0
R90 "CRCW02010000Z0ED" 0201_Silk 2007.63,2943 r0 top value=0
R91 "CRCW02010000Z0ED" 0201_Silk 2230.07,2943 r0 top value=0
R92 "CRCW02010000Z0ED" 0201_Silk 2230.07,2843 r0 top value=0
R93 "CRCW02010000Z0ED" 0201_Silk 2007.63,2843 r180 top value=0
R94 "CRCW02010000Z0ED" 0201_Silk 2007.63,2743 r180 top value=0
R95 "CRCW040210K0FKED" 0402L 2230.37,2899.06 r0 top value=10.0k
R96 "ERJ-2GE0R00X" 0402 362.62,1589.53 r180 bottom value=0
R97 "CRCW04024K99FKED" 0402L 2021.27,2073.8 r0 bottom value=4.99k
R98 "CRCW04024K99FKED" 0402L 2023.27,2003.8 r0 bottom value=4.99k
R99 "CRCW02010000Z0ED" 0201_Silk 1703.26,2056.8 r180 bottom value=0
R100 "CRCW02010000Z0ED" 0201_Silk 1703.26,2021.8 r180 bottom value=0
R101 "CRCW04023R83FKED" 0402L 1692.69,2210.88 r90 bottom value=3.83
R102 "CRCW04023R83FKED" 0402L 2032.22,2229.46 r90 bottom value=3.83
R103 "CRCW04023R83FKED" 0402L 1689.22,1836.46 r270 bottom value=3.83
R104 "CRCW04023R83FKED" 0402L 2034.22,1839.46 r270 bottom value=3.83
R105 "ERJ-2GEJ102X" 0402L 2114.37,1969.06 r270 bottom value=1.0k
R106 "ERJ-2GE0R00X" 0402L 1601.72,2362.46 r0 bottom value=0
R107 "ERJ-2RKF4991X" 0402L 2076.27,1968.8 r270 bottom value=4.99k
R108 "ERJ-2RKF4991X" 0402L 2123.37,2074.06 r180 bottom value=4.99k
R109 "CRCW040210K0FKED" 0402L 2149.37,1969.06 r90 bottom value=10.0k
R110 "CRCW040210K0FKED" 0402L 2121.68,2040.46 r180 bottom value=10.0k
R111 "CRCW0402100KFKED" 0402L 1601.41,2324.46 r0 bottom value=100k
R112 "CRCW04021K96FKED" 0402L 2122.37,2108.06 r180 bottom value=1.96k
R113 "CRCW20100000Z0EF" 2010 746.37,1584.06 r270 top value=0
R114 "ERJ-2GEJ511X" 0402L 2651.37,1781.06 r180 bottom value=510
R115 "CRCW20100000Z0EF" 2010 693,1001 r270 top value=0
R116 "CRCW20100000Z0EF" 2010 2323,551 r90 bottom value=0
R117 "ERJ-2GEJ511X" 0402L 2371.62,1864.53 r0 top value=510
R118 "ERJ-2GEJ511X" 0402L 2624.37,4393.06 r180 top value=510
R119 "ERJ-2GEJ101X" 0402L 2456,2587 r270 bottom value=100
R120 "CRCW040210K0FKED" 0402L 2632.37,2038.06 r270 bottom value=10.0k
R121 "CRCW02010000Z0ED" 0201_Silk 2378.99,2583 r180 bottom value=0
R122 "PMR18EZPFV2L00" 1206 1010.3,3673.44 r180 top value=0.002
R123 "ERJ-2GEJ361X" 0402L 625.37,202.9 r90 top value=360
R124 "ERJ-2GEJ101X" 0402L 2570,2165 r0 bottom value=100
R125 "ERJ-2GEJ511X" 0402L 553,202.9 r90 top value=510
R126 "CRCW040210K0FKED" 0402L 2379,2619 r0 bottom value=10.0k
R127 "ERJ-2GEJ101X" 0402L 2559,2037.68 r90 bottom value=100
R128 "ERJ-2GEJ511X" 0402L 2455.37,4494.06 r90 top value=510
R129 "ERJ-2GEJ101X" 0402L 2710,1963 r90 bottom value=100
R130 "CRCW0402100KFKED" 0402L 2455,4460 r90 bottom value=100k
R131 "ERJ-2GE0R00X" 0402 223.06,954.08 r0 top value=0
R132 "CRCW0402750RFKED" 0402L 134.54,826.26 r180 top value=750
R133 "CRCW040210K0FKED" 0402L 194.68,887.05 r270 top value=10.0k
R134 "CRCW04027K87FKED" 0402L 194.68,805.99 r270 top value=7.87k
R135 "CRCW040282K5FKED" 0402L 133.54,861.27 r0 top value=82.5k
R136 "CRCW0402750RFKED" 0402L 254.54,861.27 r180 top value=750
R137 "CRCW040210K0FKED" 0402L 254.37,826.26 r0 top value=10.0k
R138 "CRCW04027K87FKED" 0402L 317.18,805.99 r270 top value=7.87k
R139 "CRCW040282K5FKED" 0402L 317.18,887.05 r270 top value=82.5k
R140 "CRCW0402750RFKED" 0402L 434.59,895.45 r90 top value=750
R141 "CRCW040210K0FKED" 0402L 375.81,853.64 r0 top value=10.0k
R142 "CRCW04027K87FKED" 0402L 434.59,815.45 r270 top value=7.87k
R143 "CRCW040282K5FKED" 0402L 375.81,818.64 r0 top value=82.5k
R144 "ERJ-2GE0R00X" 0402 527,1855 r180 top value=0
R145 "ERJ-2GE0R00X" 0402 362.62,1640.53 r180 bottom locked value=0
R146 "ERJ-2GE0R00X" 0402 363.87,1691.53 r180 bottom value=0
R147 "RCS06030000Z0EA" 0603 886.91,2794.85 r90 top value=0
R148 "CRCW0402510RJNED" 0402 856.1,2956.8 r270 bottom value=510
R149 "ERJ-2RKF1003X" 0402 820,2675 r90 bottom value=100k
R150 "ERJ-2GE0R00X" 0402L 1059.92,2789.93 r180 bottom value=0
R151 "CRCW040210K0FKED" 0402L 1406.35,2563.13 r180 top value=10.0k
R152 "CRCW0402330KFKED" 0402L 2451.11,3410.87 r270 top value=330k
R153 "CRCW040230K0FKED" 0402L 2544.37,3485.6 r270 bottom value=30.0k
R154 "MCT06030Z0000ZP500" 0603 2459.37,3378.62 r180 bottom value=0
R155 "CRCW0402330KFKED" 0402L 2474.37,3505.06 r180 bottom value=330k
R156 "MCT06030Z0000ZP500" 0603 2498.62,3149.06 r90 bottom value=0
R157 "ERJ-2GE0R00X" 0402 1068.37,3623.06 r0 bottom value=0
R158 "ERJ-2GE0R00X" 0402L 1795,3005 r0 bottom value=0
R159 "ERJ-2GEJ101X" 0402L 1680.49,2923.76 r270 bottom value=100
R160 "ERJ-2GE0R00X" 0402 1068.37,3673.06 r0 bottom value=0
R161 "CRCW02010000Z0ED" 0201_Silk 995,3463 r0 top value=0
R162 "CRCW02010000Z0ED" 0201_Silk 995,3500 r0 top value=0
R163 "CRCW04021K00FKED" 0402L 1625.49,3673.76 r90 bottom value=1.00k
R164 "CRCW04021K00FKED" 0402L 1590.49,3673.76 r90 bottom value=1.00k
R165 "CRCW04021K00FKED" 0402L 1555.49,3673.76 r90 bottom value=1.00k
R166 "CRCW04021K00FKED" 0402L 1515.49,3673.76 r90 bottom value=1.00k
R167 "CRCW040249R9FKED" 0402L 1227.37,2850.06 r0 bottom value=49.9
R168 "CRCW040210K0FKED" 0402L 966.8,3258.99 r0 bottom value=10.0k
R169 "CRCW04021K00FKED" 0402L 965,3209 r0 bottom value=1.00k
R170 "CRCW04024K87FKED" 0402L 1475.49,3673.76 r270 bottom value=4.87k
R171 "CRCW02010000Z0ED" 0201_Silk 398.74,2087.66 r90 bottom value=0
R172 "CRCW02010000Z0ED" 0201_Silk 1565.39,2005.62 r90 top value=0
R173 "CRCW02010000Z0ED" 0201_Silk 1592.68,2149.37 r0 top value=0
R174 "CRCW02010000Z0ED" 0201_Silk 398.74,2157.66 r90 bottom value=0
R175 "CRCW02010000Z0ED" 0201_Silk 1650,2082.99 r90 top value=0
R176 "CRCW040210K0FKED" 0402L 314.69,2057.58 r180 bottom value=10.0k
R177 "CRCW040210K0FKED" 0402L 1585.08,2113.82 r180 bottom value=10.0k
R178 "CRCW02010000Z0ED" 0201_Silk 294.37,2256.06 r90 bottom value=0
R179 "ERJ-2GE0R00X" 0402L 334.43,2227.8 r90 bottom value=0
R180 "ERJ-2GE0R00X" 0402L 1674.58,2002.2 r270 top value=0
R181 "ERJ-2GE0R00X" 0402 1835,2740 r180 top value=0
R182 "CRCW040233R2FKED" 0402 1582.78,3604.18 r90 top value=33.2
R183 "CRCW040233R2FKED" 0402 1532.78,3604.18 r90 top value=33.2
R184 "ERJ-2GE0R00X" 0402 1479.59,3604.18 r90 top value=0
R185 "CRCW040210K0FKED" 0402 1600,2740 r180 top value=10.0k
R186 "CRCW040210K0FKED" 0402 1705,2740 r0 top value=10.0k
R187 "CRCW040210K0FKED" 0402 1600,2790 r180 top value=10.0k
R188 "CRCW040233R2FKED" 0402 1339.85,3669.59 r90 bottom value=33.2
R189 "CRCW040210K0FKED" 0402 1357.78,3709.18 r90 top value=10.0k
R190 "CRCW040210K0FKED" 0402 1302.78,3709.18 r90 top value=10.0k
R191 "ERJ-2GEJ511X" 0402 2610.37,4265.06 r0 bottom value=510
R192 "ERJ-2GE0R00X" 0402 1262.78,3604.18 r90 top value=0
R193 "CRCW04022K20JNED" 0402 1705,2790 r0 top value=2.2k
R194 "ERJ-2GE0R00X" 0402 1369.78,3604.18 r90 top value=0
R195 "ERJ-2GE0R00X" 0402 1319.78,3604.18 r90 top value=0
R196 "ERJ-2GE0R00X" 0402 1212.37,3684.06 r90 top value=0
R197 "CRCW040233R2FKED" 0402 1210.49,3692.39 r90 bottom value=33.2
R198 "ERJ-2GE0R00X" 0402 1047.5,3572.06 r180 top value=0
R199 "ERJ-2GE0R00X" 0402 980,3405 r180 top value=0
R200 "ERJ-2GE0R00X" 0402 976.85,3299.15 r180 top value=0
R201 "CRCW040210K0FKED" 0402 1665,3210 r180 top value=10.0k
R202 "ERJ-2GE0R00X" 0402 976.37,3399.06 r180 bottom value=0
R203 "CRCW040210K0FKED" 0402L 810,2340 r180 bottom value=10.0k
R204 "ERJ-2GEJ102X" 0402 1609,3474 r270 top value=1.0k
R205 "ERJ-2GE0R00X" 0402 976.85,3299.15 r180 bottom value=0
R206 "CRCW040233R2FKED" 0402 976.85,3199.15 r180 top value=33.2
R207 "ERJ-2GE0R00X" 0402 971.85,3149.15 r180 top value=0
R208 "CRCW040233R2FKED" 0402 976.85,3094.15 r180 top value=33.2
R209 "CRCW040210K0FKED" 0402L 1310.37,2418.06 r180 top value=10.0k
R210 "ERJ-2GE0R00X" 0402 1157.78,2860.18 r270 top value=0
R211 "ERJ-2GE0R00X" 0402 1207.93,2860.18 r270 top value=0
R212 "CRCW040233R2FKED" 0402 1285.37,2843.06 r0 top value=33.2
R213 "CRCW040233R2FKED" 0402 1285.37,2891.06 r0 top value=33.2
R214 "CRCW040233R2FKED" 0402 1360.37,2873.06 r270 top value=33.2
R215 "ERJ-2GE0R00X" 0402 1421.93,2860.18 r270 top value=0
R216 "ERJ-2GE0R00X" 0402 1472.93,2860.18 r270 top value=0
R217 "ERJ-2GE0R00X" 0402 1523.37,2860.06 r270 top value=0
R218 "CRCW040233R2FKED" 0402 980,3350 r180 top value=33.2
R219 "CRCW08050000Z0EA" 0805_HV 2509.37,4137.06 r90 bottom value=0
R220 "CRCW08050000Z0EA" 0805 2413.01,4131.86 r90 bottom value=0
R221 "CRCW08050000Z0EA" 0805 1127.09,2642.53 r180 top value=0
R222 "CRCW040249K9FKED" 0402 1220,2621.38 r90 bottom value=49.9k
R223 "CRCW040230K0FKED" 0402 2430,4045 r0 top value=30.0k
R224 "ERJ-2GE0R00X" 0402 160,3178 r180 bottom value=0
R225 "CRCW040229K4FKED" 0402 1400,2651.19 r90 bottom value=29.4k
R226 "CRCW0402100KFKED" 0402 1184.75,2769.06 r0 bottom value=100k
R227 "ERJ-2GE0R00X" 0402 2484.37,3832.06 r0 bottom value=0
R228 "CRCW0402100KFKED" 0402 1275.51,2756.19 r270 bottom value=100k
R229 "ERJ-2GE0R00X" 0402 527.62,1904.53 r180 top value=0
R230 "ERJ-2GE0R00X" 0402 363.62,1742.53 r180 bottom value=0
R231 "ERJ-2GE0R00X" 0402 364.62,1793.53 r180 bottom value=0
R232 "PMR18EZPFV2L00" 1206 556.77,4524.06 r270 bottom value=0.002
R233 "ERJ-2GE0R00X" 0402 1209.37,749.06 r0 top value=0
R234 "ERJ-2GE0R00X" 0402 1166.37,787.06 r180 bottom value=0
R235 "PMR18EZPFV2L00" 1206 771.37,3316.06 r90 bottom value=0.002
R236 "ERJ-2GE0R00X" 0402 335.62,1340.53 r90 bottom value=0
R237 "ERJ-2GE0R00X" 0402 144.62,1233.53 r180 bottom value=0
R238 "ERJ-2GE0R00X" 0402 386.62,1340.53 r90 bottom value=0
R239 "ERJ-2GE0R00X" 0402 143,1286 r0 bottom value=0
R240 "ERJ-2GE0R00X" 0402 1926.63,4163 r270 bottom value=0
R241 "CRCW04024K70JNED" 0402 143.57,1335.99 r0 bottom value=4.7k
R242 "ERJ-2GEJ101X" 0402 361.62,1262.53 r0 bottom value=100
R243 "CRCW04024K70JNED" 0402 528.26,1243.95 r0 top value=4.7k
R244 "CRCW04024K70JNED" 0402 143.62,1384.53 r0 bottom value=4.7k
R245 "ERJ-2GEJ101X" 0402 143.57,1434.42 r0 bottom value=100
R246 "ERJ-2GE0R00X" 0402 528.26,1293.95 r180 top value=0
R247 "CRCW0402100KFKED" 0402L 1854.01,4633.99 r90 bottom value=100k
R248 "CRCW0402100KFKED" 0402L 2081.5,4390.15 r180 bottom value=100k
R249 "CRCW0402100KFKED" 0402L 1838.5,4252.35 r0 bottom value=100k
R250 "CRCW040210K0FKED" 0402L 837.37,2164.37 r90 bottom value=10.0k
R251 "ERJ-2GEJ511X" 0402 829,217 r270 top value=510
R252 "ERJ-2GEJ511X" 0402 898,217 r270 top value=510
R253 "ERJ-2GEJ511X" 0402 969.5,217 r270 top value=510
R254 "CRCW04021K60JNED" 0402 2615.37,4337.06 r180 bottom value=1.6k
R255 "CRCW0402750RFKED" 0402 694.26,217 r90 top value=750
R256 "CRCW12060000Z0EA" 1206 1091.37,1576.06 r180 top value=0
R260 "CRCW040210K0FKED" 0402L 2231.75,1785.05 r0 top value=10.0k
R261 "CRCW04024K70JNED" 0402 2354.3,1822.5 r180 top value=4.7k
R262 "CRCW04024K70JNED" 0402 1360,2285 r180 bottom value=4.7k
R268 "ERJ-2GE0R00X" 0402 528.26,1648.95 r180 top value=0
R269 "ERJ-2GE0R00X" 0402 528.26,1703.95 r180 top value=0
R270 "ERJ-2GE0R00X" 0402 528.26,1753.95 r180 top value=0
R271 "CRCW040210K0JNED" 0402 1864.37,1309.06 r90 top value=10k
R272 "CRCW040210K0JNED" 0402 1844.37,954.06 r180 top value=10k
R273 "ERJ-2GE0R00X" 0402 1312.99,749.06 r0 top value=0
R274 "CRCW040210K0FKED" 0402 2069.01,4567.99 r180 bottom value=10.0k
R275 "CRCW040210K0FKED" 0402 1720.01,4712.99 r180 bottom value=10.0k
R276 "ERJ-2GE0R00X" 0402 160,3129 r180 bottom value=0
R281 "ERJ-2GE0R00X" 0402 2090.63,4301 r0 bottom value=0
R283 "ERJ-2GE0R00X" 0402 2091.63,4351 r0 bottom value=0
R286 "PMR18EZPFV2L00" 1206 2053.22,1599.46 r0 bottom value=0.002
R287 "PMR18EZPFV2L00" 1206 2000.26,2498.95 r90 bottom value=0.002
R288 "PMR18EZPFV2L00" 1206 1672.09,1606.1 r180 bottom value=0.002
R289 "PMR18EZPFV2L00" 1206 1661.27,2443.8 r180 bottom value=0.002
R290 "ERJ-2GE0R00X" 0402 1400.28,2756.19 r90 bottom value=0
R291 "PMR18EZPFV2L00" 1206 2439.37,1934.06 r0 top value=0.002
R293 "CRCW0402220RJNED" 0402 2644.37,752.06 r90 bottom value=220
R294 "ERJ-2GE0R00X" 0402 1304.99,736.85 r180 bottom value=0
R295 "ERJ-2GE0R00X" 0402 1418.96,734.82 r0 bottom value=0
R296 "ERJ-2GE0R00X" 0402 1343.78,784.06 r180 bottom value=0
R297 "ERJ-2GE0R00X" 0402 1803.48,719.8 r0 bottom value=0
R298 "ERJ-2GE0R00X" 0402 1557.85,729.06 r180 bottom value=0
R299 "CRCW040210K0FKED" 0402L 2274.37,1619.06 r180 top value=10.0k
R301 "CRCW040210K0FKED" 0402L 1881.37,2520.06 r180 top value=10.0k
R303 "CRCW02010000Z0ED" 0201 2380,1687.01 r90 top value=0
R304 "CRCW02010000Z0ED" 0201 1915.91,2668.35 r0 top value=0
R305 "CRCW02010000Z0ED" 0201 2206.38,1566.69 r180 bottom value=0
R306 "CRCW02010000Z0ED" 0201 1917.09,2627.01 r0 top value=0
R307 "CRCW040210K0FKED" 0402L 2315,1755 r0 top value=10.0k
R308 "CRCW040210K0FKED" 0402L 2320.82,1696.33 r0 top value=10.0k
R309 "CRCW040210K0JNED" 0402 1145.37,892.06 r180 bottom value=10k
R310 "CRCW040210K0FKED" 0402L 1924.09,2591.69 r180 top value=10.0k
R311 "CRCW040210K0FKED" 0402L 1924.09,2556.69 r180 top value=10.0k
R312 "CRCW040210K0JNED" 0402 1539.37,839.06 r270 top value=10k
